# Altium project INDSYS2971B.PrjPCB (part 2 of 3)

## Sheet INDSYS2971B_BiasPower.SchDoc
size 431 x 279 mm; Date: Not shown in title block; ApprovedBy: Not shown in title block; CheckedBy: Not shown in title block; Author: Not shown in title block; CompanyName: Not shown in title block; DrawnBy: Battery test; Engineer: Not shown in title block; Organization: Not shown in title block; Address1: Not shown in title block; Address2: Not shown in title block; Address3: Not shown in title block; Address4: Not shown in title block; DocumentNumber: 10; Revision: Use project parameter SCH_Rev; SheetNumber: 10; SheetTotal: 11; PageSetup: Record=PageOptions¦CenterHorizontal=True¦CenterVertical=True¦PrintScale=1.00¦XCorrection=1.00¦YCorrection=1.00¦PrintKind=0¦BorderSize=5000000¦LeftOffset=0¦BottomOffset=0¦Orientation=2¦PaperLength=1000¦PaperWidth=1000¦Scale=100¦PaperSource=15¦PrintQuality=600¦MediaType=1¦DitherType=10¦PaperKind=Letter¦PrintScaleMode=1
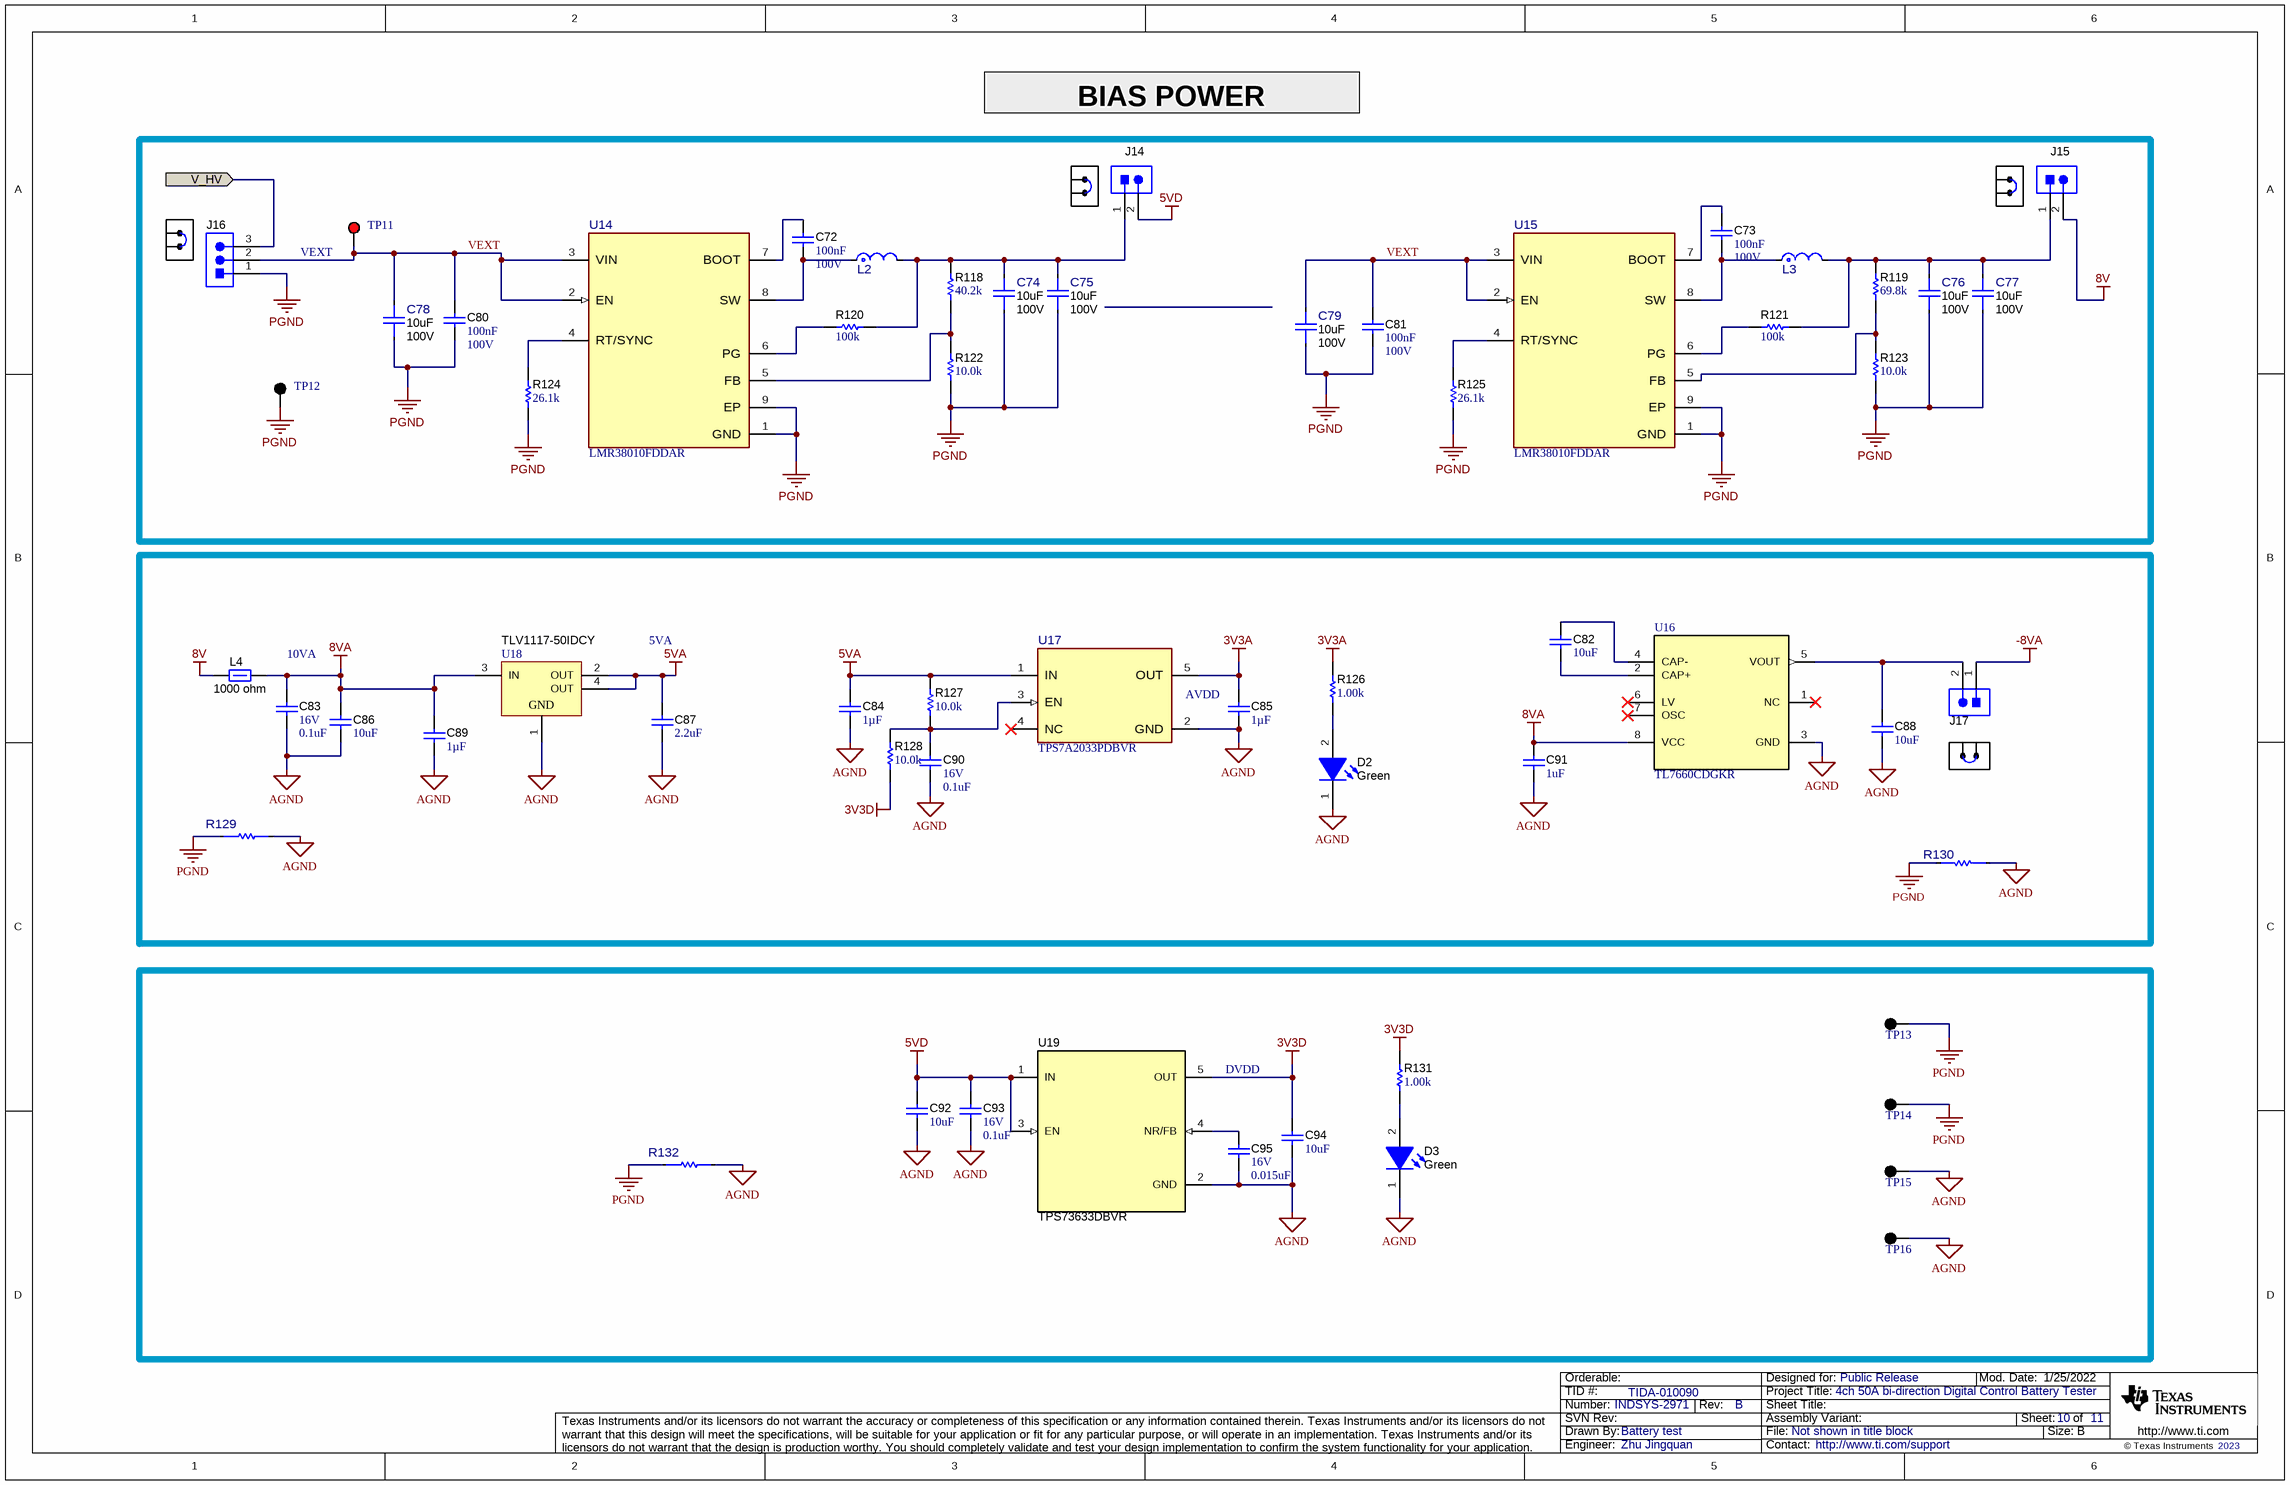
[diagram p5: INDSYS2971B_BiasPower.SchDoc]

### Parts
C72  Cap_F: 100nF  VDC_V: 100V  [0603]  (hidden comment: GRM188R72A104KA35D)
C73  Cap_F: 100nF  VDC_V: 100V  [0603]  (hidden comment: GRM188R72A104KA35D)
C74  ValueDisplayed: 10uF  VDC_V: 100V  [FP-GRM32EC72A106KE05L_1210-MFG]  (hidden comment: GRM32EC72A106KE05L)
C75  ValueDisplayed: 10uF  VDC_V: 100V  [FP-GRM32EC72A106KE05L_1210-MFG]  (hidden comment: GRM32EC72A106KE05L)
C76  ValueDisplayed: 10uF  VDC_V: 100V  [FP-GRM32EC72A106KE05L_1210-MFG]  (hidden comment: GRM32EC72A106KE05L)
C77  ValueDisplayed: 10uF  VDC_V: 100V  [FP-GRM32EC72A106KE05L_1210-MFG]  (hidden comment: GRM32EC72A106KE05L)
C78  ValueDisplayed: 10uF  VDC_V: 100V  [FP-GRM32EC72A106KE05L_1210-MFG]  (hidden comment: GRM32EC72A106KE05L)
C79  ValueDisplayed: 10uF  VDC_V: 100V  [FP-GRM32EC72A106KE05L_1210-MFG]  (hidden comment: GRM32EC72A106KE05L)
C80  Cap_F: 100nF  VDC_V: 100V  [0603]  (hidden comment: GRM188R72A104KA35D)
C81  Cap_F: 100nF  VDC_V: 100V  [0603]  (hidden comment: GRM188R72A104KA35D)
C82  ValueDisplayed: 10uF  [0603]  (hidden comment: GRM188R61E106MA73D)
C83  VDC_V: 16V  ValueDisplayed: 0.1uF  [0402]  (hidden comment: GRM155R61C104KA88D)
C84  ValueDisplayed: 1µF  [0603S]  (hidden comment: CGA3E1X7R1E105K080AC)
C85  ValueDisplayed: 1µF  [0603S]  (hidden comment: CGA3E1X7R1E105K080AC)
C86  ValueDisplayed: 10uF  [0603]  (hidden comment: GRM188R61E106MA73D)
C87  ValueDisplayed: 2.2uF  [0603S]  (hidden comment: F381A225MMA)
C88  ValueDisplayed: 10uF  [0603]  (hidden comment: GRM188R61E106MA73D)
C89  ValueDisplayed: 1µF  [0603S]  (hidden comment: CGA3E1X7R1E105K080AC)
C90  VDC_V: 16V  ValueDisplayed: 0.1uF  [0402]  (hidden comment: GRM155R61C104KA88D)
C91  ValueDisplayed: 1uF  [0805_HV]  (hidden comment: C2012X7S2A105K125AB)
C92  ValueDisplayed: 10uF  [0603]  (hidden comment: GRM188R61E106MA73D)
C93  VDC_V: 16V  ValueDisplayed: 0.1uF  [0402]  (hidden comment: GRM155R61C104KA88D)
C94  ValueDisplayed: 10uF  [0603]  (hidden comment: GRM188R61E106MA73D)
C95  VDC_V: 16V  ValueDisplayed: 0.015uF  [0402]  (hidden comment: GRM155R71C153KA01D)
D2  value Green  [WL-SMCW_GREEN]  (hidden comment: 150060VS75000)
D3  value Green  [WL-SMCW_GREEN]  (hidden comment: 150060VS75000)
J14  HTSW-102-07-G-S  [Samtec_HTSW-102-07-G-S]  (value not drawn)
J15  HTSW-102-07-G-S  [Samtec_HTSW-102-07-G-S]  (value not drawn)
J16  HTSW-103-07-G-S  [Samtec_HTSW-103-07-G-S]  (value not drawn)
J17  HTSW-102-07-G-S  [Samtec_HTSW-102-07-G-S]  (value not drawn)
L2  XGL6060-223MEC  [FP-XGL6060-223MEC_SMT2_6MM51_6MM71-MFG]  (value not drawn)
L3  XGL6060-223MEC  [FP-XGL6060-223MEC_SMT2_6MM51_6MM71-MFG]  (value not drawn)
L4  value 1000 ohm  [1806_HighSpeed]  (hidden comment: BLM41PG102SN1L)
R118  ValueDisplayed: 40.2k  [0402]  (hidden comment: CRCW040240K2FKED)
R119  ValueDisplayed: 69.8k  [0402]  (hidden comment: MCR01MZPF6982)
R120  ValueDisplayed: 100k  [0402]  (hidden comment: RC0402FR-07100KL)
R121  ValueDisplayed: 100k  [0402]  (hidden comment: RC0402FR-07100KL)
R122  ValueDisplayed: 10.0k  [0402]  (hidden comment: ERJPA2F1002X)
R123  ValueDisplayed: 10.0k  [0402]  (hidden comment: ERJPA2F1002X)
R124  ValueDisplayed: 26.1k  [0603]  (hidden comment: RC0603FR-0726K1L)
R125  ValueDisplayed: 26.1k  [0603]  (hidden comment: RC0603FR-0726K1L)
R126  ValueDisplayed: 1.00k  [0402]  (hidden comment: ERA-2AEB102X)
R127  ValueDisplayed: 10.0k  [0402]  (hidden comment: PCF0402-12-10K0BT1)
R128  ValueDisplayed: 10.0k  [0402]  (hidden comment: PCF0402-12-10K0BT1)
R129  CRCW12060000Z0EAC  [FP-CRCW12060000Z0EAC_1206-MFG]  (value not drawn)
R130  CRCW12060000Z0EAC  [FP-CRCW12060000Z0EAC_1206-MFG]  (value not drawn)
R131  ValueDisplayed: 1.00k  [0402]  (hidden comment: ERA-2AEB102X)
R132  CRCW12060000Z0EAC  [FP-CRCW12060000Z0EAC_1206-MFG]  (value not drawn)
SH-J2  60900213421  [Wurth_60900213421]  (value not drawn)
SH-J3  60900213421  [Wurth_60900213421]  (value not drawn)
SH-J4  60900213421  [Wurth_60900213421]  (value not drawn)
SH-J5  60900213421  [Wurth_60900213421]  (value not drawn)
TP11  5000  [Keystone5000]  (value not drawn)
TP12  5001  [Keystone5001]  (value not drawn)
TP13  5001  [Keystone5001]  (value not drawn)
TP14  5001  [Keystone5001]  (value not drawn)
TP15  5001  [Keystone5001]  (value not drawn)
TP16  5001  [Keystone5001]  (value not drawn)
U14  LMR38010FDDAR  [DDA0008E-MFG]
U15  LMR38010FDDAR  [DDA0008E-MFG]
U16  TL7660CDGKR  [DGK0008A_N]
U17  TPS7A2033PDBVR  [DBV0005A-MFG]
U18  PartNumber: TLV1117-50IDCY  [DCY0004A_N]  (hidden comment: TLV1117LV30DCYR)
U19  TPS73633DBVR  [DBV0005A_N]

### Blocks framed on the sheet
VEXT: C72-C81 J14-J16 L2 L3 R118-R125 SH-J2-SH-J4 TP11 TP12 U14 U15
DVDD: C92-C95 D3 R131 R132 TP13-TP16 U19

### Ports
V_HV (in)

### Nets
3V3A: C85.1 R126.2 U17.5(OUT)
3V3D: C94.1 R128.1 R131.2 U19.5(OUT)
5VA: C84.1 C87.1 R127.2 U17.1(IN) U18.2(OUT) U18.4(OUT)
5VD: C92.1 C93.2 J14.2 U19.1(IN) U19.3(EN)
8V: J15.2 L4.1
8VA: C83.2 C86.1 C89.1 C91.1 L4.2 U16.8(VCC) U18.3(IN)
-8VA: J17.1
AGND: C83.1 C84.2 C85.2 C86.2 C87.2 C88.2 C89.2 C90.1 C91.2 C92.2 C93.1 C94.2 C95.2 D2.1(K) D3.1(K) R129.2 R130.1 R132.2 TP15.1 TP16.1 U16.3(GND) U17.2(GND) U18.1(GND) U19.2(GND)
PGND: C74.1 C75.1 C76.1 C77.1 C78.1 C79.1 C80.2 C81.2 J16.1 R122.1 R123.1 R124.1 R125.1 R129.1 R130.2 R132.1 TP12.1 TP13.1 TP14.1 U14.1(GND) U14.9(EP) U15.1(GND) U15.9(EP)
V_HV: J16.3 ; port V_HV
VEXT: C78.2 C79.2 C80.1 C81.1 J16.2 TP11.1 U14.2(EN) U14.3(VIN) U15.2(EN) U15.3(VIN)
NetC72_1: C72.1 U14.7(BOOT)
NetC72_2: C72.2 L2.1 U14.8(SW)
NetC73_1: C73.1 U15.7(BOOT)
NetC73_2: C73.2 L3.1 U15.8(SW)
NetC74_2: C74.2 C75.2 J14.1 L2.2 R118.2 R120.2
NetC76_2: C76.2 C77.2 J15.1 L3.2 R119.2 R121.2
NetC82_1: C82.1 U16.4(CAP-)
NetC82_2: C82.2 U16.2(CAP+)
NetC88_1: C88.1 J17.2 U16.5(VOUT)
NetC90_2: C90.2 R127.1 R128.2 U17.3(EN)
NetC95_1: C95.1 U19.4(NR/FB)
NetD2_2: D2.2(A) R126.1
NetD3_2: D3.2(A) R131.1
NetR118_1: R118.1 R122.2 U14.5(FB)
NetR119_1: R119.1 R123.2 U15.5(FB)
NetR120_1: R120.1 U14.6(PG)
NetR121_1: R121.1 U15.6(PG)
NetR124_2: R124.2 U14.4(RT/SYNC)
NetR125_2: R125.2 U15.4(RT/SYNC)

Not connected (* = marked no-connect by the designer): U16 1(NC)* 6(LV)* 7(OSC)*; U17 4(NC)*

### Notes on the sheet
- BIAS POWER
- 10VA
- 5VA
- (near U17) AVDD

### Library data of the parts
C72 C73 C80 C81 = CMP-0007469-4: CAP, CERM, 0.1 uF, 100 V, +/- 10%, X7R, 0603; Manufacturer: MuRata; TaMin_C: -55°C; Polarized: N; SizeAreaWB_mm2: 4.68; Value1: Unknown; U/M: EA; Value: 0.1uF; TaMax_C: 125°C; SizeZ_mm: 1; SizeX_mm: 1.6; SizeY_mm: 0.8; SizeArea_mm2: 1.28; AEC Category: Q200
C74-C79 = CMP-0087970-1: 10µF ±10% 100V Ceramic Capacitor X7S 1210 (3225 Metric); Manufacturer: Murata; Symbol Name: SYM-GRM32EC72A106KE05L; AEC Qualified: No; TempCo: 22%; SizeZ_mm: 2.7mm
C82 C86 C88 C92 C94 = CMP-0007344-5: CAP, CERM, 10 uF, 25 V, +/- 20%, X5R, 0603; Manufacturer: MuRata; Polarized: N; Value: 10uF; U/M: EA; Cap_F: 10µF; Value1: Unknown; VDC_V: 25V; TaMin_C: -55°C; TaMax_C: 85°C; SizeArea_mm2: 1.28; SizeAreaWB_mm2: 4.68; SizeX_mm: 1.6; SizeY_mm: 0.8; SizeZ_mm: 1; AEC Category: Q200
C83 C90 C93 = CMP-0006591-2: CAP, CERM, 0.1 uF, 16 V, +/- 10%, X5R, 0402; Manufacturer: MuRata; TaMin_C: -55°C; Polarized: N; SizeAreaWB_mm2: 3; Value1: Unknown; U/M: EA; Value: 0.1uF; TaMax_C: 85°C; SizeZ_mm: 0.6; SizeX_mm: 1; SizeY_mm: 0.5; Cap_F: 100nF; AEC Category: Q200
C84 C85 C89 = CMP-0076705-3: CAP, CERM, 1 µF, 25 V,+/- 10%, X7R, AEC-Q200 Grade 1, 0603; Manufacturer: TDK; Polarized: N; Value: 1uF; U/M: EA; VDC_V: 25V; TaMin_C: -55°C; TaMax_C: 125°C; Cap_Case: 1.6x0.8x0.8mm; SizeAreaWB_mm2: 4.68; SizeArea_mm2: 1.28; AEC Qualified: Y; AEC Category: Q200; SizeZ_mm: 1.0; AEC Grade: 1; SizeY_mm: 0.8; SizeX_mm: 1.6
C87 = CMP-0076705-3: CAP TANT POLY 2.2UF 10V 0603; Manufacturer: KYOCERA AVX; Polarized: N; U/M: EA; Tolerance_%: 20%; ESR_ohm: 0.2; TempCo: X7R; TaMin_C: -55°C; TaMax_C: 125°C; Cap_Case: 1.6x0.8x0.8mm; SizeAreaWB_mm2: 4.68; SizeArea_mm2: 1.28; AEC Qualified: Y; AEC Category: Q200; SizeZ_mm: 1.0; AEC Grade: 1; SizeY_mm: 0.8; SizeX_mm: 1.6
C91 = CMP-0007891-2: CAP, CERM, 1 uF, 100 V, +/- 10%, X7S, 0805; Manufacturer: TDK; Polarized: N; Value: 1uF; U/M: EA; Cap_F: 1µF; ESR_ohm: 8.255m; Value1: 0.008255 ohm; VDC_V: 100V; IRMS_A: 2.2744A; TaMin_C: -55°C; TaMax_C: 125°C; Cap_Case: 0805; AEC Category: Q200; SizeArea_mm2: 2.5; SizeAreaWB_mm2: 6.75; SizeX_mm: 2; SizeY_mm: 1.25; SizeZ_mm: 1.45
C95 = CMP-0006644-2: CAP, CERM, 0.015 uF, 16 V, +/- 10%, X7R, 0402; Manufacturer: MuRata; TaMin_C: -55°C; Polarized: N; SizeAreaWB_mm2: 3; Value1: Unknown; U/M: EA; TaMax_C: 125°C; SizeZ_mm: 0.6; SizeX_mm: 1; SizeY_mm: 0.5; Cap_F: 15nF; AEC Category: Q200
D2 D3 = CMP-0002894-2: LED, Green, SMD; Manufacturer: Wurth Elektronik; Type: AlInGaP; Vf_V: 2V; Io_A: 20mA; Value1: W
J14 J15 J17 = CMP-0075483-1: Header, 100mil, 2x1, Gold, TH; Manufacturer: Samtec; Green_REACh: Passed; CT: False; Green_Lifecycle: Active; CNHeader: True
J16 = CMP-0075484-1: Header, 100mil, 3x1, Gold, TH; Manufacturer: Samtec; Green_REACh: Passed; CT: False; Green_Lifecycle: Active; CNHeader: True
L2 L3 = CMP-0095453-1: 22 µH Shielded Inductor 5.8 A 46.9mOhm Max Nonstandard; Manufacturer: Coilcraft; Isat: 2.5A; Test Frequency: 1MHz; SizeZ_mm: 6.1mm; Self Resonant Frequency: 9MHz; Value: 22uH; Irms: 5.8A; DCR_ohm: 46.9m; Ind_H: 22µH; Material: Composite; AEC Qualified: Yes; AEC Grade: Grade 1; TaMax_C: +125°C; Tolerance_%: 20%; Shrouded: true; TaMin_C: -40°C
L4 = CMP-0003369-1: Ferrite Bead, 1000 ohm @ 100 MHz, 1.5 A, 1806; Manufacturer: MuRata; ZTyp@100MHz_Ohm: 1k; SizeAreaWB_mm2: 14.3; DCR_ohm: 0.09; Value1: 0.09 ohm; Imax_A: 1.5A; SizeZ_mm: 1.85; SizeX_mm: 4.5; SizeY_mm: 1.6; SizeArea_mm2: 7.2
R118 = CMP-0026367-2: RES, 40.2 k, 1%, 0.063 W, AEC-Q200 Grade 0, 0402; Manufacturer: Vishay-Dale; Power_W: 63mW; TempCo: 100 ppm/C; Value_Code: 40k2; Value: 40.2k; EIA_Code: E96; SizeX_mm: 1; SizeY_mm: 0.5; SizeZ_mm: 0.6; Value2: 0.063W; AEC Qualified: Y; VDC_V: 50V; AEC Category: Q200; AEC Grade: 0
R119 = CMP-0026720-1: RES, 69.8 k, 1%, 0.063 W, 0402; Manufacturer: Rohm; Power_W: 63mW; TempCo: 100 ppm/C; Value_Code: 69k8; U/M: EA; Value: 69.8k; EIA_Code: E96; SizeX_mm: 1; SizeY_mm: 0.5; SizeZ_mm: 0.6; Value2: 0.063W; AEC Qualified: N; VDC_V: 50V; AEC Category: Q200
R120 R121 = CMP-0026721-1: RES, 100 k, 1%, 0.0625 W, 0402; Manufacturer: Yageo America; Power_W: 62.5mW; TempCo: 100 ppm/C; U/M: EA; Value: 100k; EIA_Code: E96; SizeX_mm: 1; SizeY_mm: 0.5; SizeZ_mm: 0.6; AEC Qualified: N; VDC_V: 50V; AEC Category: Q200
R122 R123 = CMP-0078779-1: RES, 10.0 k, 1%, 0.2 W, AEC-Q200 Grade 0, 0402; Manufacturer: Panasonic; Value_Code: 10k0; SizeArea_mm2: 0.5; AEC Qualified: Y; AEC Category: Q200; Res_ohm: 10k; Value: 10.0k; SizeZ_mm: 0.6; EIA_Code: E96; TempCo: 100 ppm/C; AEC Grade: 0; Power_W: 200mW; VDC_V: 50V; Value2: 0.2W; SizeX_mm: 1
R124 R125 = CMP-0022957-5: RES, 26.1 k, 1%, 0.1 W, 0603; Manufacturer: Yageo; Power_W: 100mW; TempCo: 100 ppm/C; Value_Code: 26k1; Value: 26.1k; EIA_Code: E96; SizeX_mm: 1.6; SizeY_mm: 0.8; SizeZ_mm: 1; Value2: 0.1W; SizeArea_mm2: 1.28; AEC Qualified: N; VDC_V: 75V; AEC Category: Q200; SizeAreaWB_mm2: 4.68
R126 R131 = CMP-0026770-1: RES, 1.00 k, 0.1%, 0.063 W, 0402; Manufacturer: Panasonic; Power_W: 63mW; TempCo: 25 ppm/C; Value_Code: 1k00; U/M: EA; Value: 1.00k; EIA_Code: E192; Res_ohm: 1k; SizeX_mm: 1; SizeY_mm: 0.5; SizeZ_mm: 0.6; Value2: 0.063W; VDC_V: 50V; AEC Category: Q200
R127 = CMP-0026796-1: RES, 10.0 k, 0.1%, 0.063 W, 0402; Manufacturer: TT Electronics/IRC; Power_W: 63mW; TempCo: 10 ppm/C; Value_Code: 10k0; Value: 10.0k; Res_ohm: 10k; SizeX_mm: 1; SizeY_mm: 0.5; SizeZ_mm: 0.6; Value2: 0.063W; AEC Qualified: N; VDC_V: 25V; AEC Category: Q200; EIA_Code: E192; U/M: EA
R128 = CMP-0026796-1: RES, 10.0 k, 0.1%, 0.063 W, 0402; Manufacturer: TT Electronics/IRC; Power_W: 63mW; TempCo: 10 ppm/C; Value_Code: 10k0; Value: 10.0k; EIA_Code: E192; Res_ohm: 10k; SizeX_mm: 1; SizeY_mm: 0.5; SizeZ_mm: 0.6; Value2: 0.063W; AEC Qualified: N; VDC_V: 25V; AEC Category: Q200; U/M: EA
R129 R130 R132 = CMP-0094724-1: Jumper 0.25W, 1/4W Chip Resistor 1206 (3216 Metric) - Thick Film; Manufacturer: Vishay; Value: 0; Power_W: 250mW; VDC_V: 200V; SizeZ_mm: 0.65mm; AEC Qualified: No
SH-J2-SH-J5 = CMP-0003761-2: Shunt, 2.54mm, Gold, Black; Manufacturer: Wurth Elektronik
TP11 = CMP-0055137-2: Test Point, Miniature, Red, TH; Manufacturer: Keystone Electronics; Green_REACh: Passed; Green_Lifecycle: Active; ContactFinish: Silver; CNHeader: FALSE; CT: TRUE
TP12-TP16 = CMP-0055138-2: Test Point, Miniature, Black, TH; Manufacturer: Keystone Electronics; ContactFinish: Silver; Green_Lifecycle: Active; Green_REACh: Passed; CNHeader: FALSE; CT: TRUE
U14 U15 = CMP-0096892-1: 4.2-V to 80-V, 1-A Synchronous Buck Converter with 40-µA IQ; Manufacturer: Texas Instruments; Output Type: AdjustableProgrammable; AEC Qualified: No; Output Voltage: 1-75V; Standoff Height: 0mm; Nominal Supply Current: 40uA; Number Of Outputs: 1; TJmax_C: +150°C; Switching Frequency: 200-2200kHz; Min Supply Voltage: 4.2V; Max Duty Cycle: 97%; Max Supply Voltage: 80V; SizeZ_mm: 1.7mm
U16 = CMP-0041281-2: CMOS Voltage Converter, DGK0008A (VSSOP-8); Manufacturer: Texas Instruments; Total Supply Voltage(Min)(+5V is 5, +/-5V is 10): 1.5; Sub Family: Low Power Amp (<=500uA), Low Supply Voltage Amplifier (<=2.7V), Precision Amplifier; Total Supply Voltage(Max)(+5V is 5, +/-5V is 10): 10; Iq per channel(Max)(mA): 0.11; Number of Channels: 1; AEC Category: Q200; AEC Qualified: N; CompType: IC; SizeAreaWB_mm2: 23.6; SizeArea_mm2: 14.7; SizeX_mm: 4.9; SizeY_mm: 3; SizeZ_mm: 1.1
U17 = CMP-0092532-1: 300-mA, Ultra-Low-Noise, Low-IQ, High PSRR LDO; Manufacturer: Texas Instruments; TJmax_C: +125°C; Min Supply Voltage: 1.6V; SizeZ_mm: 1.45mm; Output Voltage: 3.3V; Number Of Outputs: 1; Nominal Supply Current: 6.5uA; AEC Qualified: No; Accuracy Percentage: 1.5%; Max Supply Voltage: 6V; Dropout Voltage: 145mV; Standoff Height: 0mm; Output Type: Fixed
U18 = CMP-0036758-1: Single Output LDO, 1 A, Fixed 5 V Output, 2 to 5.5 V Input, 4-pin SOT-223 (DCY), -40 to 125 degC, Green (RoHS & no Sb/Br); Manufacturer: Texas Instruments; Vout Adj(Max)(V): 3; Iq(Typ)(mA): 0.05; Vin(Max)(V): 5.5; Accuracy(%): 2; SubFamily: Single Channel LDO; Vdo(Typ)(mV): 1200; Iout(Max)(A): 1
U19 = CMP-0036866-2: Single Output Low Noise LDO, 400 mA, Fixed 3.3 V Output, 1.7 to 5.5 V Input, with Reverse Current Protection, 5-pin SOT-23 (DBV), -40 to 85 degC, Green (RoHS & no Sb/Br); Manufacturer: Texas Instruments; Alternate PartNumber: TPS73633DBVT; Vout Adj(Min)(V): 3.3; Rating: Catalog; Accuracy(%): 1; Iq(Typ)(mA): 0.3; Vin(Max)(V): 5.5; SubFamily: Single Channel LDO; Vdo(Typ)(mV): 75; Vin(Min)(V): 1.7; Iout(Max)(A): 0.4; AEC Category: Q200; AEC Qualified: N; CompType: IC; Green_Lifecycle: Active; Green_REACh: Passed; SizeAreaWB_mm2: 14.82; SizeArea_mm2: 8.12; SizeX_mm: 2.8; SizeY_mm: 2.9; SizeZ_mm: 1.45

## Sheet INDSYS2971B_ControlCard.SchDoc
size 431 x 279 mm; Date: Not shown in title block; ApprovedBy: Not shown in title block; CheckedBy: Not shown in title block; Author: Not shown in title block; CompanyName: Not shown in title block; DrawnBy: Battery test; Engineer: Not shown in title block; Organization: Not shown in title block; Address1: Not shown in title block; Address2: Not shown in title block; Address3: Not shown in title block; Address4: Not shown in title block; DocumentNumber: 9; Revision: Use project parameter SCH_Rev; SheetNumber: 9; SheetTotal: 11; PageSetup: Record=PageOptions¦CenterHorizontal=True¦CenterVertical=True¦PrintScale=1.00¦XCorrection=1.00¦YCorrection=1.00¦PrintKind=0¦BorderSize=5000000¦LeftOffset=0¦BottomOffset=0¦Orientation=2¦PaperLength=1000¦PaperWidth=1000¦Scale=100¦PaperSource=15¦PrintQuality=600¦MediaType=1¦DitherType=10¦PaperKind=Letter¦PrintScaleMode=1
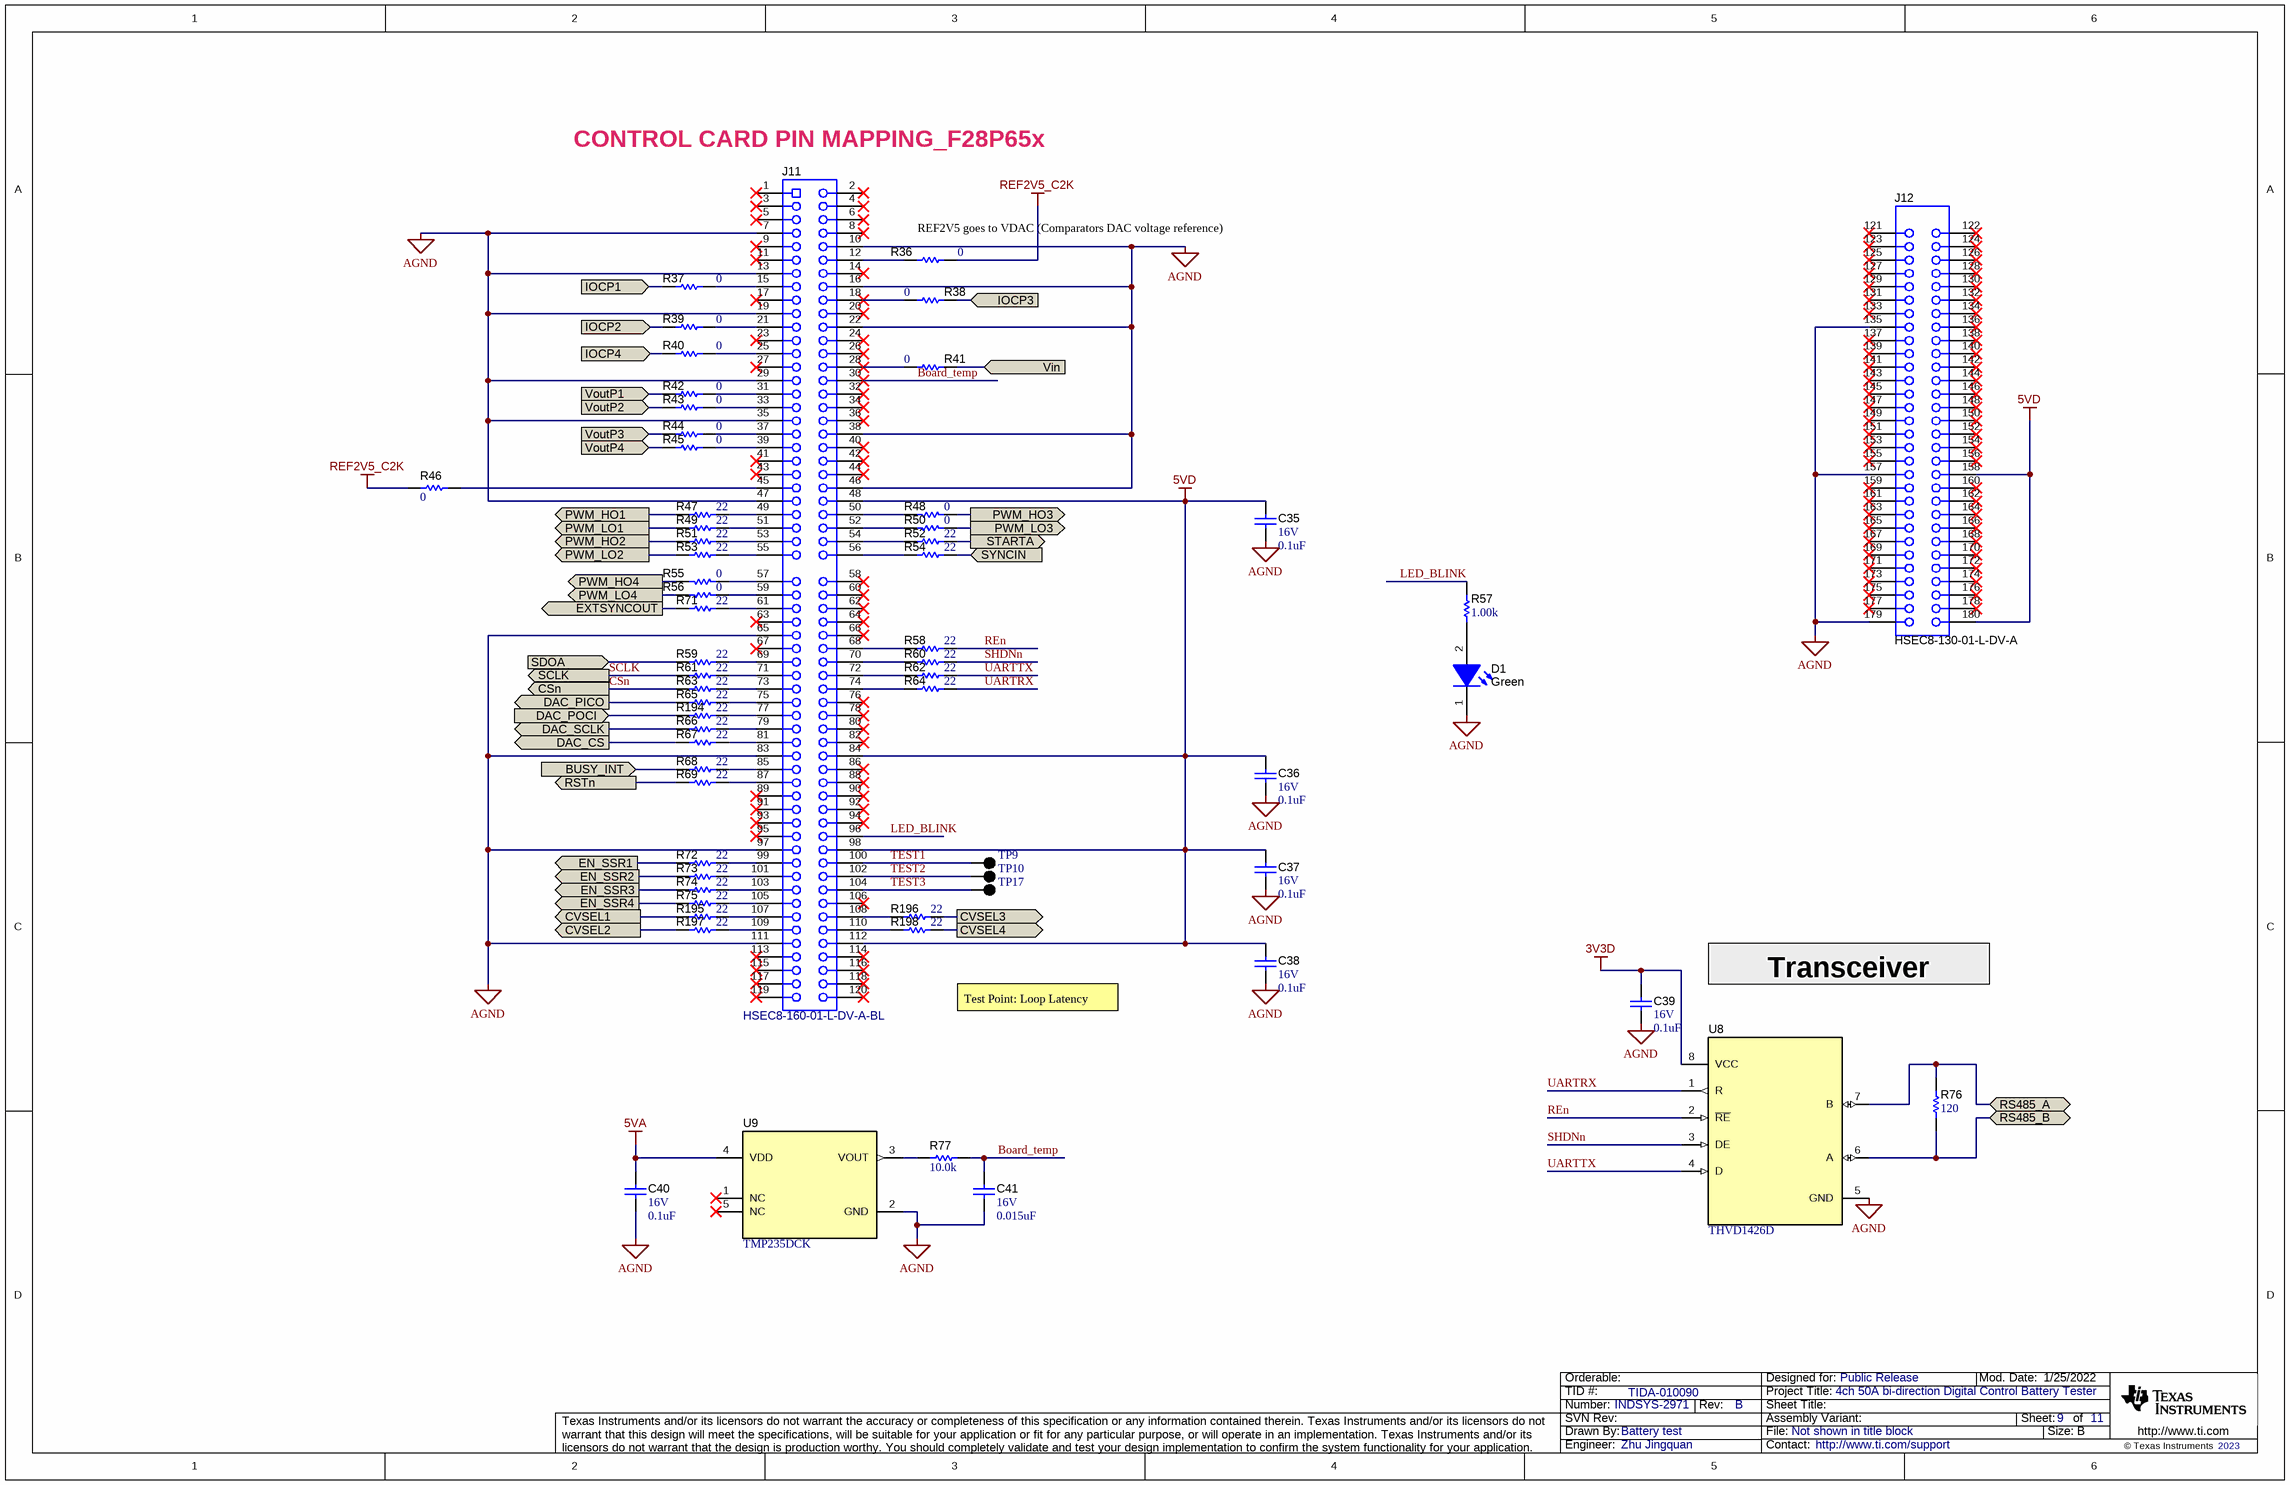
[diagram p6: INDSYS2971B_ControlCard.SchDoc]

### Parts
C35  VDC_V: 16V  ValueDisplayed: 0.1uF  [0402]  (hidden comment: GRM155R61C104KA88D)
C36  VDC_V: 16V  ValueDisplayed: 0.1uF  [0402]  (hidden comment: GRM155R61C104KA88D)
C37  VDC_V: 16V  ValueDisplayed: 0.1uF  [0402]  (hidden comment: GRM155R61C104KA88D)
C38  VDC_V: 16V  ValueDisplayed: 0.1uF  [0402]  (hidden comment: GRM155R61C104KA88D)
C39  VDC_V: 16V  ValueDisplayed: 0.1uF  [0402]  (hidden comment: GRM155R61C104KA88D)
C40  VDC_V: 16V  ValueDisplayed: 0.1uF  [0402]  (hidden comment: GRM155R61C104KA88D)
C41  VDC_V: 16V  ValueDisplayed: 0.015uF  [0402]  (hidden comment: GRM155R71C153KA01D)
D1  value Green  [WL-SMCW_GREEN]  (hidden comment: 150060VS75000)
J11  HSEC8-160-01-L-DV-A-BL  [controlCARD-120HSEC]
J12  HSEC8-130-01-L-DV-A  [controlCARD-180HSEC-60pinAddon]
R36  ValueDisplayed: 0  [0402]  (hidden comment: CRCW04020000Z0ED)
R37  ValueDisplayed: 0  [0402]  (hidden comment: CRCW04020000Z0ED)
R38  ValueDisplayed: 0  [0402]  (hidden comment: CRCW04020000Z0ED)
R39  ValueDisplayed: 0  [0402]  (hidden comment: CRCW04020000Z0ED)
R40  ValueDisplayed: 0  [0402]  (hidden comment: CRCW04020000Z0ED)
R41  ValueDisplayed: 0  [0402]  (hidden comment: CRCW04020000Z0ED)
R42  ValueDisplayed: 0  [0402]  (hidden comment: CRCW04020000Z0ED)
R43  ValueDisplayed: 0  [0402]  (hidden comment: CRCW04020000Z0ED)
R44  ValueDisplayed: 0  [0402]  (hidden comment: CRCW04020000Z0ED)
R45  ValueDisplayed: 0  [0402]  (hidden comment: CRCW04020000Z0ED)
R46  ValueDisplayed: 0  [0402]  (hidden comment: CRCW04020000Z0ED)
R47  ValueDisplayed: 22  [0402]  (hidden comment: CRCW040222R0JNED)
R48  ValueDisplayed: 0  [0402]  (hidden comment: CRCW04020000Z0ED)
R49  ValueDisplayed: 22  [0402]  (hidden comment: CRCW040222R0JNED)
R50  ValueDisplayed: 0  [0402]  (hidden comment: CRCW04020000Z0ED)
R51  ValueDisplayed: 22  [0402]  (hidden comment: CRCW040222R0JNED)
R52  ValueDisplayed: 22  [0402]  (hidden comment: CRCW040222R0JNED)
R53  ValueDisplayed: 22  [0402]  (hidden comment: CRCW040222R0JNED)
R54  ValueDisplayed: 22  [0402]  (hidden comment: CRCW040222R0JNED)
R55  ValueDisplayed: 0  [0402]  (hidden comment: CRCW04020000Z0ED)
R56  ValueDisplayed: 0  [0402]  (hidden comment: CRCW04020000Z0ED)
R57  ValueDisplayed: 1.00k  [0402]  (hidden comment: ERA-2AEB102X)
R58  ValueDisplayed: 22  [0402]  (hidden comment: CRCW040222R0JNED)
R59  ValueDisplayed: 22  [0402]  (hidden comment: CRCW040222R0JNED)
R60  ValueDisplayed: 22  [0402]  (hidden comment: CRCW040222R0JNED)
R61  ValueDisplayed: 22  [0402]  (hidden comment: CRCW040222R0JNED)
R62  ValueDisplayed: 22  [0402]  (hidden comment: CRCW040222R0JNED)
R63  ValueDisplayed: 22  [0402]  (hidden comment: CRCW040222R0JNED)
R64  ValueDisplayed: 22  [0402]  (hidden comment: CRCW040222R0JNED)
R65  ValueDisplayed: 22  [0402]  (hidden comment: CRCW040222R0JNED)
R66  ValueDisplayed: 22  [0402]  (hidden comment: CRCW040222R0JNED)
R67  ValueDisplayed: 22  [0402]  (hidden comment: CRCW040222R0JNED)
R68  ValueDisplayed: 22  [0402]  (hidden comment: CRCW040222R0JNED)
R69  ValueDisplayed: 22  [0402]  (hidden comment: CRCW040222R0JNED)
R71  ValueDisplayed: 22  [0402]  (hidden comment: CRCW040222R0JNED)
R72  ValueDisplayed: 22  [0402]  (hidden comment: CRCW040222R0JNED)
R73  ValueDisplayed: 22  [0402]  (hidden comment: CRCW040222R0JNED)
R74  ValueDisplayed: 22  [0402]  (hidden comment: CRCW040222R0JNED)
R75  ValueDisplayed: 22  [0402]  (hidden comment: CRCW040222R0JNED)
R76  ValueDisplayed: 120  [0402]  (hidden comment: CRCW0402120RJNED)
R77  ValueDisplayed: 10.0k  [0402]  (hidden comment: PCF0402-12-10K0BT1)
R194  ValueDisplayed: 22  [0402]  (hidden comment: CRCW040222R0JNED)
R195  ValueDisplayed: 22  [0402]  (hidden comment: CRCW040222R0JNED)
R196  ValueDisplayed: 22  [0402]  (hidden comment: CRCW040222R0JNED)
R197  ValueDisplayed: 22  [0402]  (hidden comment: CRCW040222R0JNED)
R198  ValueDisplayed: 22  [0402]  (hidden comment: CRCW040222R0JNED)
TP9  5001  [Keystone5001]  (value not drawn)
TP10  5001  [Keystone5001]  (value not drawn)
TP17  5001  [Keystone5001]  (value not drawn)
U8  THVD1426D  [D0008A_N]
U9  TMP235DCK  [DCK0005A_N]

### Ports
BUSY_INT (in), CSn (out), CVSEL1 (out), CVSEL2 (out), CVSEL3 (out), CVSEL4 (out), DAC_CS (out), DAC_PICO (out), DAC_POCI (in), DAC_SCLK (out), EN_SSR1 (out), EN_SSR2 (out), EN_SSR3 (out), EN_SSR4 (out), EXTSYNCOUT (out), IOCP1 (in), IOCP2 (in), IOCP3 (in), IOCP4 (in), PWM_HO1 (out), PWM_HO2 (out), PWM_HO3 (out), PWM_HO4 (out), PWM_LO1 (out), PWM_LO2 (out), PWM_LO3 (out), PWM_LO4 (out), RS485_A (bidir), RS485_B (bidir), RSTn (out), SCLK (out), SDOA (in), STARTA (out), SYNCIN (in), Vin (in), VoutP1 (in), VoutP2 (in), VoutP3 (in), VoutP4 (in)

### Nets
3V3D: C39.2 U8.8(VCC)
5VA: C40.2 U9.4(VDD)
5VD: C35.2 C36.2 C37.2 C38.2 J11.48 J11.84 J11.98 J11.112 J12.158 J12.180
AGND: C35.1 C36.1 C37.1 C38.1 C39.1 C40.1 C41.2 D1.1(K) J11.7 J11.10 J11.13 J11.16 J11.19 J11.22 J11.29 J11.35 J11.38 J11.46 J11.47 J11.65 J11.83 J11.97 J11.111 J12.135 J12.157 J12.179 U8.5(GND) U9.2(GND)
REF2V5_C2K: R36.1 R46.2
Board_temp: C41.1 J11.30 R77.1
BUSY_INT: R68.1 ; port BUSY_INT
CSn: R63.1 ; port CSn
CVSEL1: R195.1 ; port CVSEL1
CVSEL2: R197.1 ; port CVSEL2
CVSEL3: R196.2 ; port CVSEL3
CVSEL4: R198.2 ; port CVSEL4
DAC_CS: R67.1 ; port DAC_CS
DAC_PICO: R65.1 ; port DAC_PICO
DAC_POCI: R194.1 ; port DAC_POCI
DAC_SCLK: R66.1 ; port DAC_SCLK
EN_SSR1: R72.1 ; port EN_SSR1
EN_SSR2: R73.1 ; port EN_SSR2
EN_SSR3: R74.1 ; port EN_SSR3
EN_SSR4: R75.1 ; port EN_SSR4
IOCP1: R37.2 ; port IOCP1
IOCP2: R39.2 ; port IOCP2
IOCP3: R38.2 ; port IOCP3
IOCP4: R40.2 ; port IOCP4
LED_BLINK: J11.96 R57.2
PWM_HO1: R47.1 ; port PWM_HO1
PWM_HO2: R51.1 ; port PWM_HO2
PWM_HO3: R48.2 ; port PWM_HO3
PWM_HO4: R55.2 ; port PWM_HO4
PWM_LO1: R49.1 ; port PWM_LO1
PWM_LO2: R53.1 ; port PWM_LO2
PWM_LO3: R50.2 ; port PWM_LO3
PWM_LO4: R56.2 ; port PWM_LO4
REn: R58.2 U8.2(~{RE})
RSTn: R69.1 ; port RSTn
SCLK: R61.1 ; port SCLK
SDOA: R59.1 ; port SDOA
SHDNn: R60.2 U8.3(DE)
STARTA: R52.2 ; port STARTA
TEST1: J11.100 TP9.1
TEST2: J11.102 TP10.1
TEST3: J11.104 TP17.1
UARTRX: R64.2 U8.1(R)
UARTTX: R62.2 U8.4(D)
Vin: R41.2 ; port Vin
VoutP1: R42.2 ; port VoutP1
VoutP2: R43.2 ; port VoutP2
VoutP3: R44.2 ; port VoutP3
VoutP4: R45.2 ; port VoutP4
NetD1_2: D1.2(A) R57.1
NetJ3_1: R76.2 U8.7(B) ; port RS485_A
NetJ3_2: R76.1 U8.6(A) ; port RS485_B
NetJ11_12: J11.12 R36.2
NetJ11_15: J11.15 R37.1
NetJ11_18: J11.18 R38.1
NetJ11_21: J11.21 R39.1
NetJ11_25: J11.25 R40.1
NetJ11_28: J11.28 R41.1
NetJ11_31: J11.31 R42.1
NetJ11_33: J11.33 R43.1
NetJ11_37: J11.37 R44.1
NetJ11_39: J11.39 R45.1
NetJ11_45: J11.45 R46.1
NetJ11_49: J11.49 R47.2
NetJ11_50: J11.50 R48.1
NetJ11_51: J11.51 R49.2
NetJ11_52: J11.52 R50.1
NetJ11_53: J11.53 R51.2
NetJ11_54: J11.54 R52.1
NetJ11_55: J11.55 R53.2
NetJ11_56: J11.56 R54.1
NetJ11_57: J11.57 R55.1
NetJ11_59: J11.59 R56.1
NetJ11_61: J11.61 R71.1
NetJ11_68: J11.68 R58.1
NetJ11_69: J11.69 R59.2
NetJ11_70: J11.70 R60.1
NetJ11_71: J11.71 R61.2
NetJ11_72: J11.72 R62.1
NetJ11_73: J11.73 R63.2
NetJ11_74: J11.74 R64.1
NetJ11_75: J11.75 R65.2
NetJ11_77: J11.77 R194.2
NetJ11_79: J11.79 R66.2
NetJ11_81: J11.81 R67.2
NetJ11_85: J11.85 R68.2
NetJ11_87: J11.87 R69.2
NetJ11_99: J11.99 R72.2
NetJ11_101: J11.101 R73.2
NetJ11_103: J11.103 R74.2
NetJ11_105: J11.105 R75.2
NetJ11_107: J11.107 R195.2
NetJ11_108: J11.108 R196.1
NetJ11_109: J11.109 R197.2
NetJ11_110: J11.110 R198.1
NetR54_2: R54.2 ; port SYNCIN
NetR71_2: R71.2 ; port EXTSYNCOUT
NetR77_2: R77.2 U9.3(VOUT)

Not connected (* = marked no-connect by the designer): J11 1* 2* 3* 4* 5* 6* 8* 9* 11* 14* 17* 20* 23* 24* 26* 27* 32* 34* 36* 40* 41* 42* 43* 44* 58* 60* 62* 63* 64* 66* 67* 76* 78* 80* 82* 86* 88* 89* 90* 91* 92* 93* 94* 95* 106* 113* 114* 115* 116* 117* 118* 119* 120*; J12 121* 122* 123* 124* 125* 126* 127* 128* 129* 130* 131* 132* 133* 134* 136* 137* 138* 139* 140* 141* 142* 143* 144* 145* 146* 147* 148* 149* 150* 151* 152* 153* 154* 155* 156* 159* 160* 161* 162* 163* 164* 165* 166* 167* 168* 169* 170* 171* 172* 173* 174* 175* 176* 177* 178*; U9 1(NC)* 5(NC)*

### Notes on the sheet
- (near J11) CONTROL CARD PIN MAPPING_F28P65x
- (near R36) REF2V5 goes to VDAC (Comparators DAC voltage reference)
- Test Point: Loop Latency
- Transceiver

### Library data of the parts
C35-C40 = CMP-0006591-2: as C83 on sheet INDSYS2971B_BiasPower
C41 = CMP-0006644-2: as C95 on sheet INDSYS2971B_BiasPower
D1 = CMP-0002894-2: as D2 on sheet INDSYS2971B_BiasPower
J11 = CMP-0003814-2: C2000 controlCARD-120HSEC connector, SMT; Manufacturer: Samtec; Note: The pin numbering does not match Samtec datasheet
J12 = CMP-0003859-2: C2000 controlCARD-180HSEC (60-pin addon) connector, SMT; Manufacturer: Samtec; Note: The pin numbering does not match Samtec datasheet
R36-R46 R48 R50 R55 R56 = CMP-0026822-3: RES, 0, 5%, 0.063 W, AEC-Q200 Grade 0, 0402; Manufacturer: Vishay-Dale; Value: 0; Value_Code: 0000; Power_W: 63mW; Value2: 0.063W; VDC_V: 50V; TempCo: 200 ppm/C; SizeArea_mm2: 0.5; SizeX_mm: 1; SizeZ_mm: 0.6; EIA_Code: E24; AEC Category: Q200; AEC Qualified: Y
R47 R49 R51-R54 R58-R69 R71-R75 R194-R198 = CMP-0026880-3: RES, 22, 5%, 0.063 W, AEC-Q200 Grade 0, 0402; Manufacturer: Vishay-Dale; Power_W: 63mW; TempCo: 200 ppm/C; Value_Code: 22R0; Value: 22; EIA_Code: E24; SizeX_mm: 1; SizeY_mm: 0.5; SizeZ_mm: 0.6; Value2: 0.063W; AEC Qualified: Y; VDC_V: 50V; AEC Category: Q200; AEC Grade: 0
R57 = CMP-0026770-1: as R126 on sheet INDSYS2971B_BiasPower
R76 = CMP-0026833-3: RES, 120, 5%, 0.063 W, AEC-Q200 Grade 0, 0402; Manufacturer: Vishay-Dale; Power_W: 63mW; TempCo: 200 ppm/C; Value_Code: 120R; Value: 120; EIA_Code: E24; SizeX_mm: 1; SizeY_mm: 0.5; SizeZ_mm: 0.6; Value2: 0.063W; AEC Qualified: Y; VDC_V: 50V; AEC Category: Q200; AEC Grade: 0
R77 = CMP-0026796-1: RES, 10.0 k, 0.1%, 0.063 W, 0402; Manufacturer: TT Electronics/IRC; Power_W: 63mW; TempCo: 10 ppm/C; Value_Code: 10k0; U/M: EA; Value: 10.0k; EIA_Code: E192; Res_ohm: 10k; SizeX_mm: 1; SizeY_mm: 0.5; SizeZ_mm: 0.6; Value2: 0.063W; AEC Qualified: N; VDC_V: 25V; AEC Category: Q200
TP9 TP10 TP17 = CMP-0055138-2: as TP12-TP16 on sheet INDSYS2971B_BiasPower
U8 = CMP-0065059-3: 3.3-V to 5-V RS-485 Transceivers with Auto-direction Control / and ±12-kV IEC ESD Protection; Manufacturer: Texas Instruments; Alternate PartNumber: THVD1426DR; SizeX_mm: 4.9; SizeY_mm: 6.2; CompType: IC; SizeZ_mm: 1.75; SizeArea_mm2: 30.38; SizeAreaWB_mm2: 56.58; AEC Category: Q200; AEC Qualified: N
U9 = CMP-0013250-3: TMP235DCK, DCK0005A (SOT-5); Manufacturer: Texas Instruments; SizeX_mm: 2.1; SizeY_mm: 2.0; CompType: IC; SizeZ_mm: 1.1; SizeArea_mm2: 4.2; SizeAreaWB_mm2: 9.3; AEC Category: Q200; AEC Qualified: N

## Sheet INDSYS2971B_Hardware.SchDoc
size 431 x 279 mm; Date: Not shown in title block; ApprovedBy: Not shown in title block; CheckedBy: Not shown in title block; Author: Not shown in title block; CompanyName: Not shown in title block; DrawnBy: Battery test; Engineer: Not shown in title block; Organization: Not shown in title block; Address1: Not shown in title block; Address2: Not shown in title block; Address3: Not shown in title block; Address4: Not shown in title block; DocumentNumber: 11; Revision: Use project parameter SCH_Rev; SheetNumber: 11; SheetTotal: 11; PageSetup: Record=PageOptions¦CenterHorizontal=True¦CenterVertical=True¦PrintScale=1.00¦XCorrection=1.00¦YCorrection=1.00¦PrintKind=0¦BorderSize=5000000¦LeftOffset=0¦BottomOffset=0¦Orientation=2¦PaperLength=1000¦PaperWidth=1000¦Scale=100¦PaperSource=15¦PrintQuality=600¦MediaType=1¦DitherType=10¦PaperKind=Letter¦PrintScaleMode=1
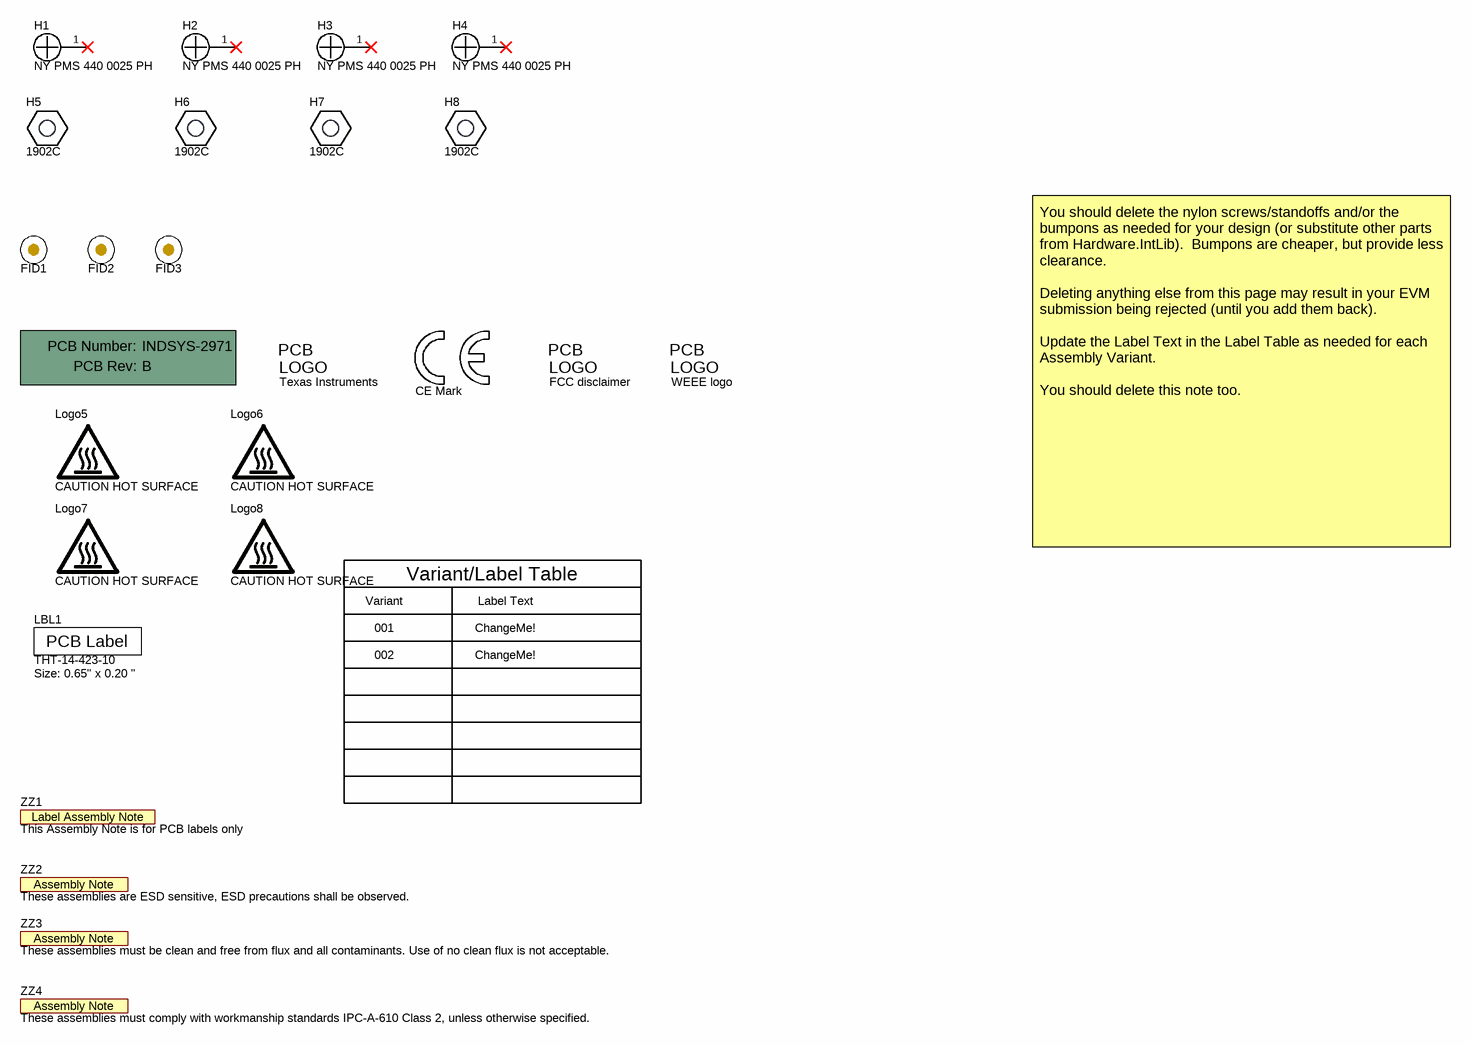
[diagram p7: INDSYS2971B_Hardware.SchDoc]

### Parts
!PCB1  Printed Circuit Board  (value not drawn)  (mechanical)
FID1  Fiducial  [Fiducial10-20]  (value not drawn)
FID2  Fiducial  [Fiducial10-20]  (value not drawn)
FID3  Fiducial  [Fiducial10-20]  (value not drawn)
H1  NY PMS 440 0025 PH  [NY PMS 440 0025 PH]
H2  NY PMS 440 0025 PH  [NY PMS 440 0025 PH]
H3  NY PMS 440 0025 PH  [NY PMS 440 0025 PH]
H4  NY PMS 440 0025 PH  [NY PMS 440 0025 PH]
H5  1902C  [Keystone_1902C]
H6  1902C  [Keystone_1902C]
H7  1902C  [Keystone_1902C]
H8  1902C  [Keystone_1902C]
LBL1  THT-14-423-10  Note: Size: 0.65" x 0.20 "  [Label_650x200]
Logo1  CE Mark  [CE_Mark_5mm]  (no BOM)
Logo2  Texas Instruments  [TI_Stacked_Overlay_Small]  (no BOM)
Logo3  FCC disclaimer  [FCC_disclaimer]  (no BOM)
Logo4  WEEE logo  [WEEE_Minimum]  (no BOM)
Logo5  CAUTION HOT SURFACE  [IEC_HotSurface_Large]  (no BOM)
Logo6  CAUTION HOT SURFACE  [IEC_HotSurface_Large]  (no BOM)
Logo7  CAUTION HOT SURFACE  [IEC_HotSurface_Large]  (no BOM)
Logo8  CAUTION HOT SURFACE  [IEC_HotSurface_Large]  (no BOM)
ZZ1  This Assembly Note is for PCB labels only  [AssemblyNoteLabel]  (no BOM)
ZZ2  These assemblies are ESD sensitive, ESD precautions shall be observed.  [AssemblyNote]  (no BOM)
ZZ3  These assemblies must be clean and free from flux and all contaminants. Use of no clean flux is not acceptable.  [AssemblyNote]  (no BOM)
ZZ4  These assemblies must comply with workmanship standards IPC-A-610 Class 2, unless otherwise specified.  [AssemblyNote]  (no BOM)

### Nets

Not connected (* = marked no-connect by the designer): H1 1*; H2 1*; H3 1*; H4 1*

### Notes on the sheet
- Variant
- Variant/Label Table
- Label Text
- You should delete the nylon screws/standoffs and/or the bumpons as needed for your design (or substitute other parts from Hardware.IntLib).  Bumpons are cheaper, but provide less clearance.
  Deleting anything else from this page may result in your EVM submission being rejected (until you add them back).
  Update the Label Text in the Label Table as needed for each Assembly Variant.
  You should delete this note too.
- 001
- 002
- ChangeMe!

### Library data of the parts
!PCB1 = CMP-0003618-2: Manufacturer: Any
FID1-FID3 = CMP-0077181-1: Fiducial mark.  There is nothing to buy or mount.
H1-H4 = CMP-0003617-1: Machine Screw, Round, #4-40 x 1/4, Nylon, Philips panhead; Manufacturer: B&F Fastener Supply; CompType: Hardware
H5-H8 = CMP-0003610-1: Standoff, Hex, 0.5"L #4-40 Nylon; Manufacturer: Keystone; CompType: Hardware
LBL1 = CMP-0003625-1: Thermal Transfer Printable Labels, 0.650" W x 0.200" H - 10,000 per roll; Manufacturer: Brady; CompType: Label
Logo1 = CMP-0074844-1: SymbolCreator: a0412235
Logo2 = CMP-0074838-1: Texas Instrument Corporate Signature; SymbolCreator: a0412235; Lib Reference: TI_Logo; Library Reference: Logo
Logo3 = CMP-0074847-1: FCC_disclaimer; Library Reference: Logo
Logo4 = CMP-0074769-3: Manufacturer: Texas Instruments; CompType: IC; AEC Category: Q200
Logo5-Logo8 = CMP-0074837-2: IEC 61010-1 Hot Surface Warning; Manufacturer: Texas Instruments; CompType: IC; AEC Category: Q200; SymbolCreator: a0412235
ZZ1 = CMP-0003616-3
ZZ2 = CMP-0077236-1
ZZ3 = CMP-0077237-1
ZZ4 = CMP-0077238-1

## Sheet INDSYS2971B_Cover.SchDoc
size 431 x 279 mm; Date: Not shown in title block; ApprovedBy: Not shown in title block; CheckedBy: Not shown in title block; Author: Not shown in title block; CompanyName: Not shown in title block; Engineer: Not shown in title block; Organization: Not shown in title block; Address1: Not shown in title block; Address2: Not shown in title block; Address3: Not shown in title block; Address4: Not shown in title block; DocumentNumber: 1; Revision: Use project parameter SCH_Rev; SheetNumber: 1; SheetTotal: 11; PageSetup: Record=PageOptions¦CenterHorizontal=True¦CenterVertical=True¦PrintScale=1.00¦XCorrection=1.00¦YCorrection=1.00¦PrintKind=0¦BorderSize=5000000¦LeftOffset=0¦BottomOffset=0¦Orientation=2¦PaperLength=1000¦PaperWidth=1000¦Scale=100¦PaperSource=15¦PrintQuality=600¦MediaType=1¦DitherType=10¦PaperKind=Letter¦PrintScaleMode=1
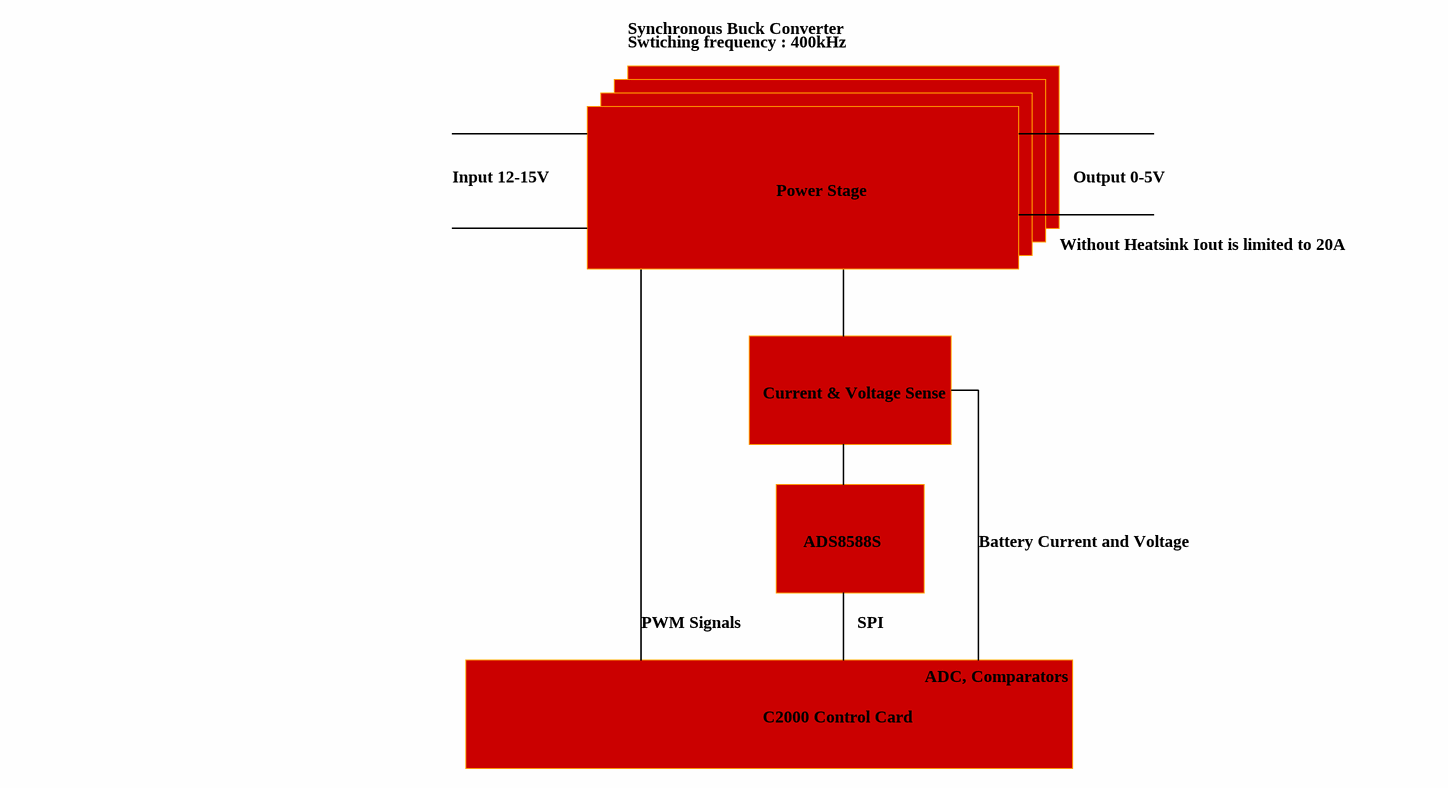
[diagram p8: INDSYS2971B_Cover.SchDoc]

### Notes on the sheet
- Synchronous Buck Converter
- Swtiching frequency : 400kHz
- Input 12-15V
- Power Stage
- Output 0-5V
- Without Heatsink Iout is limited to 20A
- Current & Voltage Sense
- ADS8588S
- Battery Current and Voltage
- PWM Signals
- SPI
- C2000 Control Card
- ADC, Comparators

## Sheet INDSYS2971B_CurrentSense.SchDoc
size 431 x 279 mm; Date: Not shown in title block; ApprovedBy: Not shown in title block; CheckedBy: Not shown in title block; Author: Not shown in title block; CompanyName: Not shown in title block; DrawnBy: Battery test; Engineer: Not shown in title block; Organization: Not shown in title block; Address1: Not shown in title block; Address2: Not shown in title block; Address3: Not shown in title block; Address4: Not shown in title block; DocumentNumber: 5; Revision: Use project parameter SCH_Rev; SheetNumber: 5; SheetTotal: 11; PageSetup: Record=PageOptions¦CenterHorizontal=True¦CenterVertical=True¦PrintScale=1.00¦XCorrection=1.00¦YCorrection=1.00¦PrintKind=0¦BorderSize=5000000¦LeftOffset=0¦BottomOffset=0¦Orientation=2¦PaperLength=1000¦PaperWidth=1000¦Scale=100¦PaperSource=15¦PrintQuality=600¦MediaType=1¦DitherType=10¦PaperKind=Letter¦PrintScaleMode=1
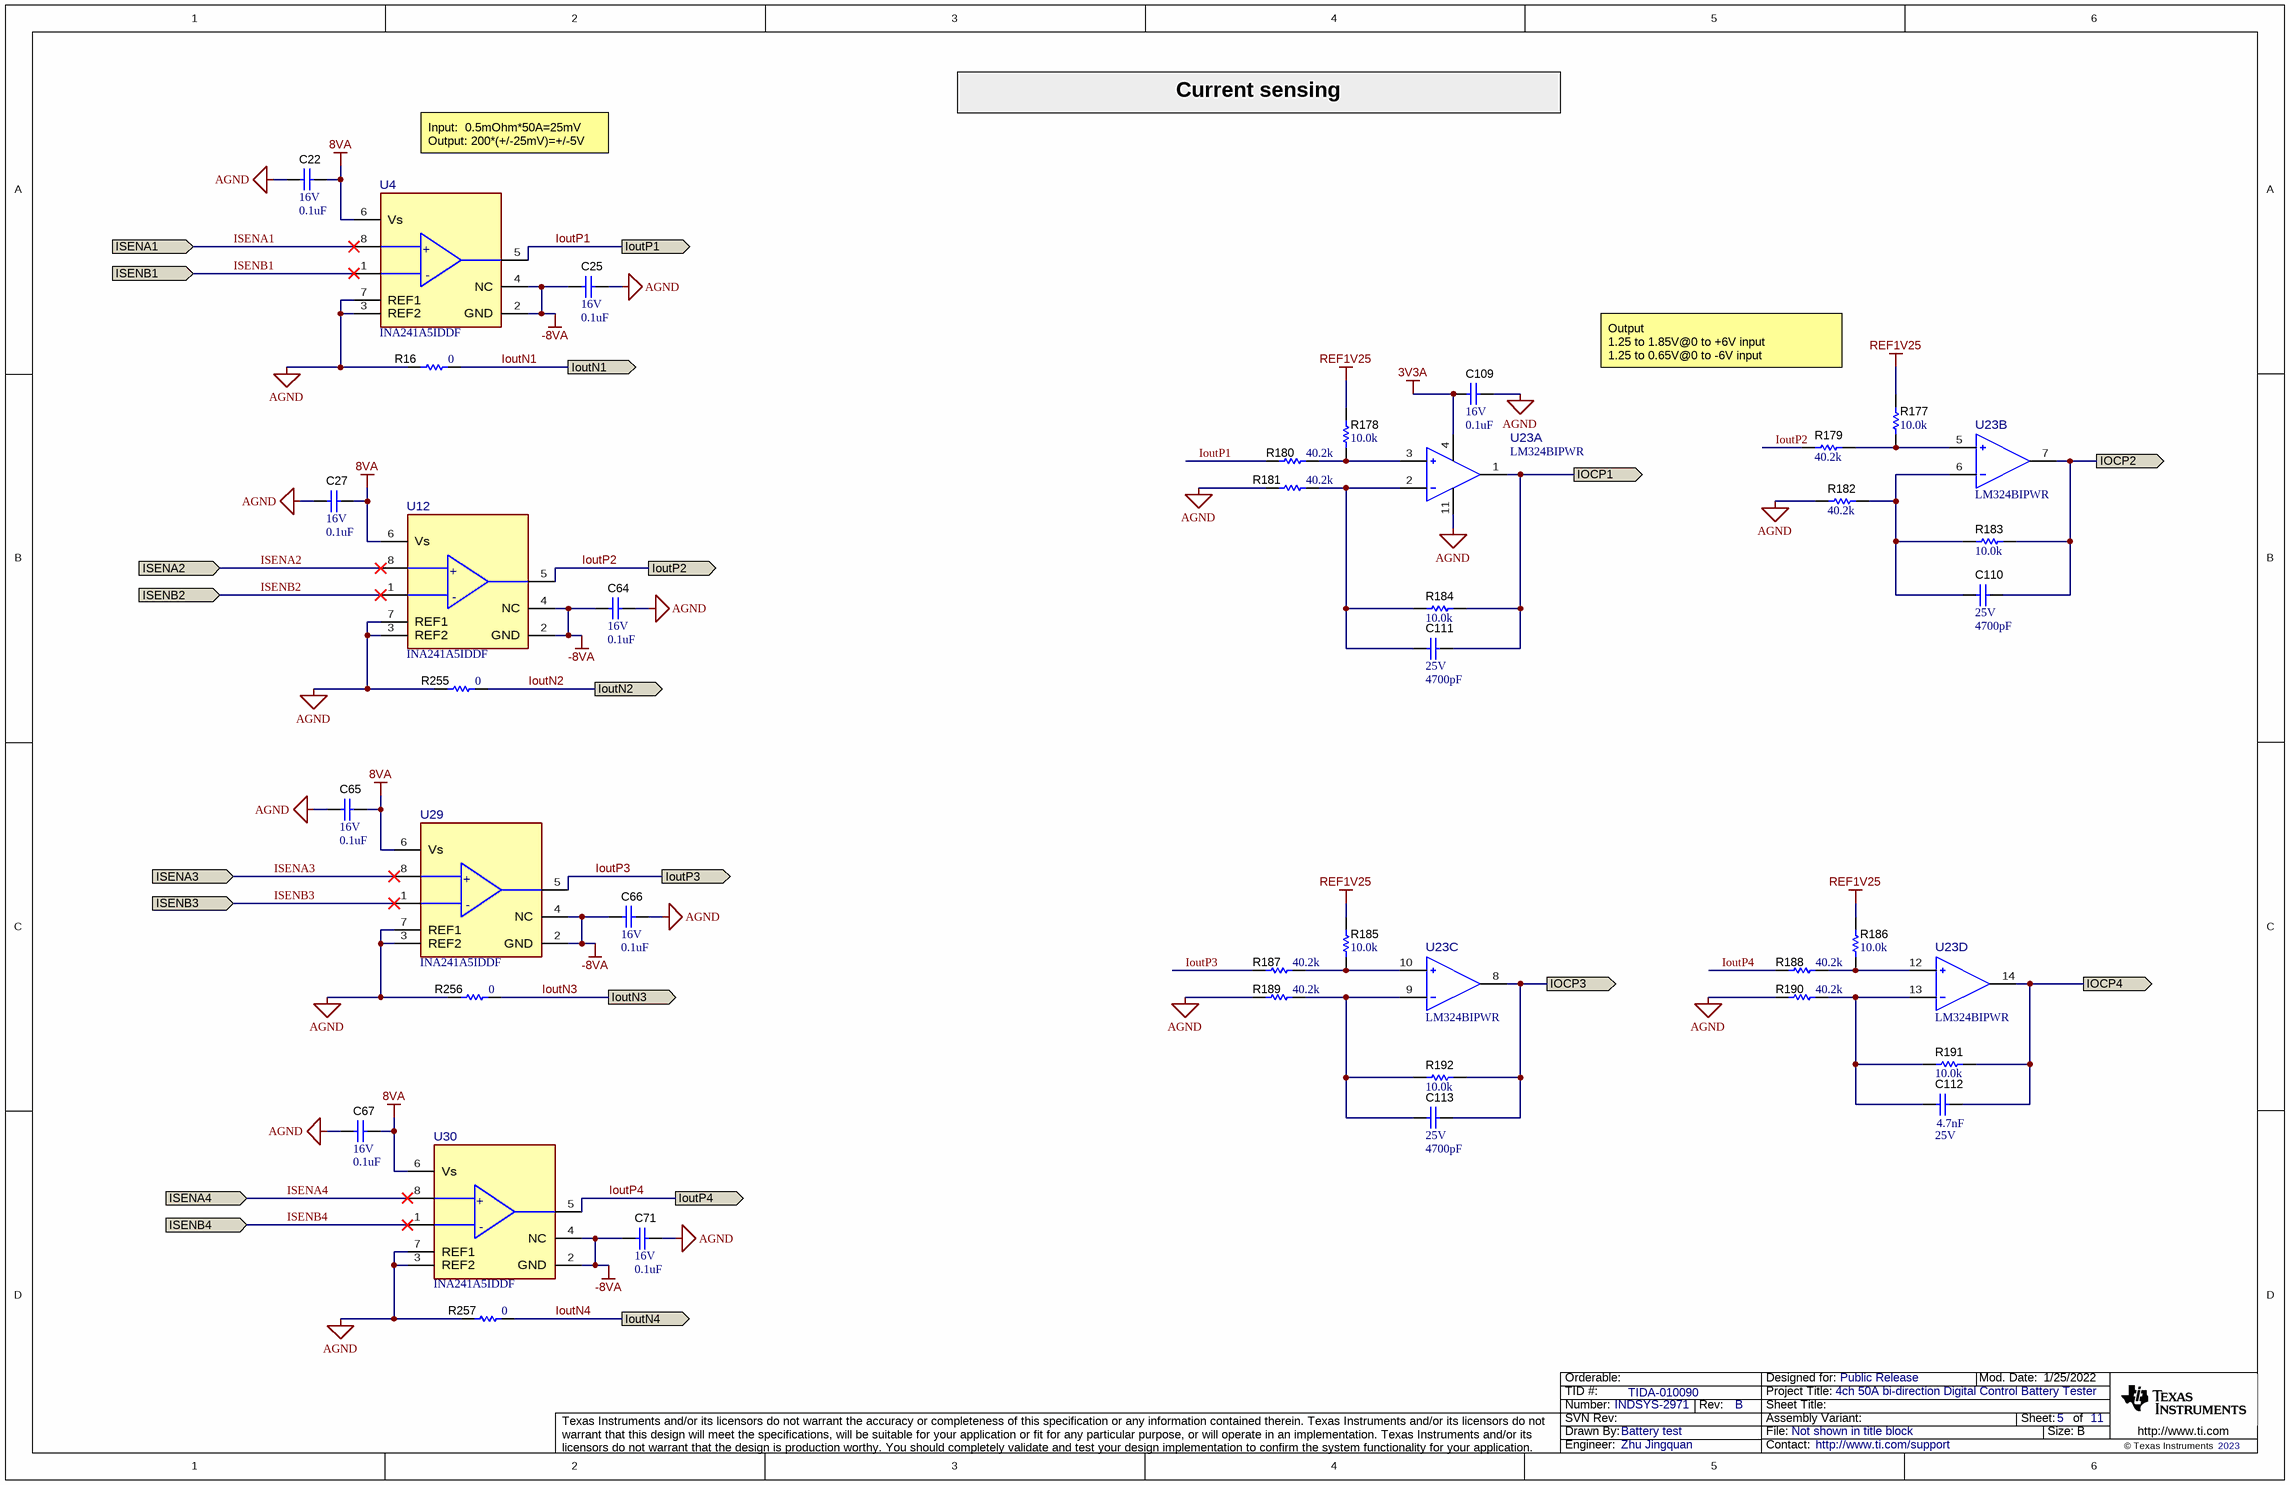
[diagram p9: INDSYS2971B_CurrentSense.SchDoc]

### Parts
C22  VDC_V: 16V  ValueDisplayed: 0.1uF  [0402]  (hidden comment: GRM155R61C104KA88D)
C25  VDC_V: 16V  ValueDisplayed: 0.1uF  [0402]  (hidden comment: GRM155R61C104KA88D)
C27  VDC_V: 16V  ValueDisplayed: 0.1uF  [0402]  (hidden comment: GRM155R61C104KA88D)
C64  VDC_V: 16V  ValueDisplayed: 0.1uF  [0402]  (hidden comment: GRM155R61C104KA88D)
C65  VDC_V: 16V  ValueDisplayed: 0.1uF  [0402]  (hidden comment: GRM155R61C104KA88D)
C66  VDC_V: 16V  ValueDisplayed: 0.1uF  [0402]  (hidden comment: GRM155R61C104KA88D)
C67  VDC_V: 16V  ValueDisplayed: 0.1uF  [0402]  (hidden comment: GRM155R61C104KA88D)
C71  VDC_V: 16V  ValueDisplayed: 0.1uF  [0402]  (hidden comment: GRM155R61C104KA88D)
C109  VDC_V: 16V  ValueDisplayed: 0.1uF  [0402]  (hidden comment: GRM155R61C104KA88D)
C110  VDC_V: 25V  ValueDisplayed: 4700pF  [0402]  (hidden comment: GRM155R61E472KA01D)
C111  VDC_V: 25V  ValueDisplayed: 4700pF  [0402]  (hidden comment: GRM155R61E472KA01D)
C112  Cap_F: 4.7nF  VDC_V: 25V  [0402]  (hidden comment: GRM155R61E472KA01D)
C113  VDC_V: 25V  ValueDisplayed: 4700pF  [0402]  (hidden comment: GRM155R61E472KA01D)
R16  ValueDisplayed: 0  [0402]  (hidden comment: CRCW04020000Z0ED)
R177  ValueDisplayed: 10.0k  [0402]  (hidden comment: PCF0402-12-10K0BT1)
R178  ValueDisplayed: 10.0k  [0402]  (hidden comment: PCF0402-12-10K0BT1)
R179  ValueDisplayed: 40.2k  [0402]  (hidden comment: CRCW040240K2FKED)
R180  ValueDisplayed: 40.2k  [0402]  (hidden comment: CRCW040240K2FKED)
R181  ValueDisplayed: 40.2k  [0402]  (hidden comment: CRCW040240K2FKED)
R182  ValueDisplayed: 40.2k  [0402]  (hidden comment: CRCW040240K2FKED)
R183  ValueDisplayed: 10.0k  [0402]  (hidden comment: PCF0402-12-10K0BT1)
R184  ValueDisplayed: 10.0k  [0402]  (hidden comment: PCF0402-12-10K0BT1)
R185  ValueDisplayed: 10.0k  [0402]  (hidden comment: PCF0402-12-10K0BT1)
R186  ValueDisplayed: 10.0k  [0402]  (hidden comment: PCF0402-12-10K0BT1)
R187  ValueDisplayed: 40.2k  [0402]  (hidden comment: CRCW040240K2FKED)
R188  ValueDisplayed: 40.2k  [0402]  (hidden comment: CRCW040240K2FKED)
R189  ValueDisplayed: 40.2k  [0402]  (hidden comment: CRCW040240K2FKED)
R190  ValueDisplayed: 40.2k  [0402]  (hidden comment: CRCW040240K2FKED)
R191  ValueDisplayed: 10.0k  [0402]  (hidden comment: PCF0402-12-10K0BT1)
R192  ValueDisplayed: 10.0k  [0402]  (hidden comment: PCF0402-12-10K0BT1)
R255  ValueDisplayed: 0  [0402]  (hidden comment: CRCW04020000Z0ED)
R256  ValueDisplayed: 0  [0402]  (hidden comment: CRCW04020000Z0ED)
R257  ValueDisplayed: 0  [0402]  (hidden comment: CRCW04020000Z0ED)
U4  INA241A5IDDF  [DDF0008A-MFG]
U12  INA241A5IDDF  [DDF0008A-MFG]
U23  LM324BIPWR  [PW0014A-MFG]  (parts A,B,C,D of 4)
U29  INA241A5IDDF  [DDF0008A-MFG]
U30  INA241A5IDDF  [DDF0008A-MFG]

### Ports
IOCP1 (out), IOCP2 (out), IOCP3 (out), IOCP4 (out), IoutN1 (out), IoutN2 (out), IoutN3 (out), IoutN4 (out), IoutP1 (out), IoutP2 (out), IoutP3 (out), IoutP4 (out), ISENA1 (in), ISENA2 (in), ISENA3 (in), ISENA4 (in), ISENB1 (in), ISENB2 (in), ISENB3 (in), ISENB4 (in)

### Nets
3V3A: C109.2 U23.4(VCC+)
8VA: C22.1 C27.1 C65.1 C67.1 U4.6(Vs) U12.6(Vs) U29.6(Vs) U30.6(Vs)
-8VA: C25.2 C64.2 C66.2 C71.2 U4.2(GND) U4.4(NC) U12.2(GND) U12.4(NC) U29.2(GND) U29.4(NC) U30.2(GND) U30.4(NC)
AGND: C22.2 C25.1 C27.2 C64.1 C65.2 C66.1 C67.2 C71.1 C109.1 R16.1 R181.1 R182.1 R189.1 R190.1 R255.1 R256.1 R257.1 U4.3(REF2) U4.7(REF1) U12.3(REF2) U12.7(REF1) U23.11(VCC-) U29.3(REF2) U29.7(REF1) U30.3(REF2) U30.7(REF1)
REF1V25: R177.2 R178.2 R185.2 R186.2
IOCP1: C111.1 R184.1 U23.1(1OUT) ; port IOCP1
IOCP2: C110.1 R183.1 U23.7(2OUT) ; port IOCP2
IOCP3: C113.1 R192.1 U23.8(3OUT) ; port IOCP3
IOCP4: C112.1 R191.1 U23.14(4OUT) ; port IOCP4
IoutN1: R16.2 ; port IoutN1
IoutN2: R255.2 ; port IoutN2
IoutN3: R256.2 ; port IoutN3
IoutN4: R257.2 ; port IoutN4
IoutP1: R180.1 U4.5(OUT) ; port IoutP1
IoutP2: R179.1 U12.5(OUT) ; port IoutP2
IoutP3: R187.1 U29.5(OUT) ; port IoutP3
IoutP4: R188.1 U30.5(OUT) ; port IoutP4
ISENA1: U4.8(IN+) ; port ISENA1
ISENA2: U12.8(IN+) ; port ISENA2
ISENA3: U29.8(IN+) ; port ISENA3
ISENA4: U30.8(IN+) ; port ISENA4
ISENB1: U4.1(IN-) ; port ISENB1
ISENB2: U12.1(IN-) ; port ISENB2
ISENB3: U29.1(IN-) ; port ISENB3
ISENB4: U30.1(IN-) ; port ISENB4
NetC110_2: C110.2 R182.2 R183.2 U23.6(2IN-)
NetC111_2: C111.2 R181.2 R184.2 U23.2(1IN-)
NetC112_2: C112.2 R190.2 R191.2 U23.13(4IN-)
NetC113_2: C113.2 R189.2 R192.2 U23.9(3IN-)
NetR177_1: R177.1 R179.2 U23.5(2IN+)
NetR178_1: R178.1 R180.2 U23.3(1IN+)
NetR185_1: R185.1 R187.2 U23.10(3IN+)
NetR186_1: R186.1 R188.2 U23.12(4IN+)

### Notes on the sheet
- Input:  0.5mOhm*50A=25mV
  Output: 200*(+/-25mV)=+/-5V
- Current sensing
- Output
  1.25 to 1.85V@0 to +6V input
  1.25 to 0.65V@0 to -6V input

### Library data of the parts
C22 C25 C27 C64-C67 C71 C109 = CMP-0006591-2: as C83 on sheet INDSYS2971B_BiasPower
C110 C111 C113 = CMP-0006611-2: CAP, CERM, 4700 pF, 25 V, +/- 10%, X5R, 0402; Manufacturer: MuRata; TaMin_C: -55°C; Polarized: N; SizeAreaWB_mm2: 3; Value1: Unknown; U/M: EA; Value: 4700pF; TaMax_C: 85°C; SizeZ_mm: 0.6; SizeX_mm: 1; SizeY_mm: 0.5; Cap_F: 4.7nF; AEC Category: Q200
C112 = CMP-0006611-2: CAP, CERM, 4700 pF, 25 V, +/- 10%, X5R, 0402; Manufacturer: MuRata; TaMin_C: -55°C; Polarized: N; SizeAreaWB_mm2: 3; Value1: Unknown; U/M: EA; Value: 4700pF; TaMax_C: 85°C; SizeZ_mm: 0.6; SizeX_mm: 1; SizeY_mm: 0.5; AEC Category: Q200
R16 R255-R257 = CMP-0026822-3: as R36-R46 on sheet INDSYS2971B_ControlCard
R177 R178 R183-R186 R191 R192 = CMP-0026796-1: as R127 on sheet INDSYS2971B_BiasPower
R179-R182 R187-R190 = CMP-0026367-2: as R118 on sheet INDSYS2971B_BiasPower
U4 U12 U29 U30 = CMP-0093651-2: -4-V to 110-V, Bidirectional, Ultra-Precise Current Sense Amplifier With Enhanced PWM Rejection; Manufacturer: Texas Instruments; Bandwidth: 1MHz; TaMax_C: +125°C; Max Supply Voltage: 20V; Nominal Supply Current: 2.5mA; Number Of Channels: 1; Min Supply Voltage: 2.7V; Input Bias Current: 40uA; Response Time: 1.5us; AEC Category: Q200; TaMin_C: -40°C; Input Offset Voltage: 0.002mV; CompType: IC; AEC Qualified: No; TJmax_C: +150°C; SizeZ_mm: 1.1mm; Standoff Height: 0mm; Voltage Gain: 0.2V/mV
U23 = CMP-0120501-1: Quad, 36-V, 1.2-MHz 3-mV offset voltage operational amplifier; Manufacturer: Texas Instruments; SizeZ_mm: 1.2mm; AEC Qualified: No; Gain Bandwidth: 1.2MHz; Input Bias Current: -0.01uA; Input Offset Voltage: 0.6mV; Max Dual Supply Voltage: 18V; Max Supply Voltage: 36V; Min Dual Supply Voltage: 2.5V; Min Supply Voltage: 5V; Nominal Supply Current: 240-350uA; Number Of Channels: 4; Output Current Per Channel: 20mA; Response Time: 4us; Standoff Height: 0.05mm; TaMax_C: +85°C; TaMin_C: -40°C; TJmax_C: +150°C; Voltage Gain: 100V/mV

## Sheet INDSYS2971B_VoltageSense.SchDoc
size 431 x 279 mm; Date: Not shown in title block; ApprovedBy: Not shown in title block; CheckedBy: Not shown in title block; Author: Not shown in title block; CompanyName: Not shown in title block; DrawnBy: Battery test; Engineer: Not shown in title block; Organization: Not shown in title block; Address1: Not shown in title block; Address2: Not shown in title block; Address3: Not shown in title block; Address4: Not shown in title block; DocumentNumber: 6; Revision: Use project parameter SCH_Rev; SheetNumber: 6; SheetTotal: 11; PageSetup: Record=PageOptions¦CenterHorizontal=True¦CenterVertical=True¦PrintScale=1.00¦XCorrection=1.00¦YCorrection=1.00¦PrintKind=0¦BorderSize=5000000¦LeftOffset=0¦BottomOffset=0¦Orientation=2¦PaperLength=1000¦PaperWidth=1000¦Scale=100¦PaperSource=15¦PrintQuality=600¦MediaType=1¦DitherType=10¦PaperKind=Letter¦PrintScaleMode=1
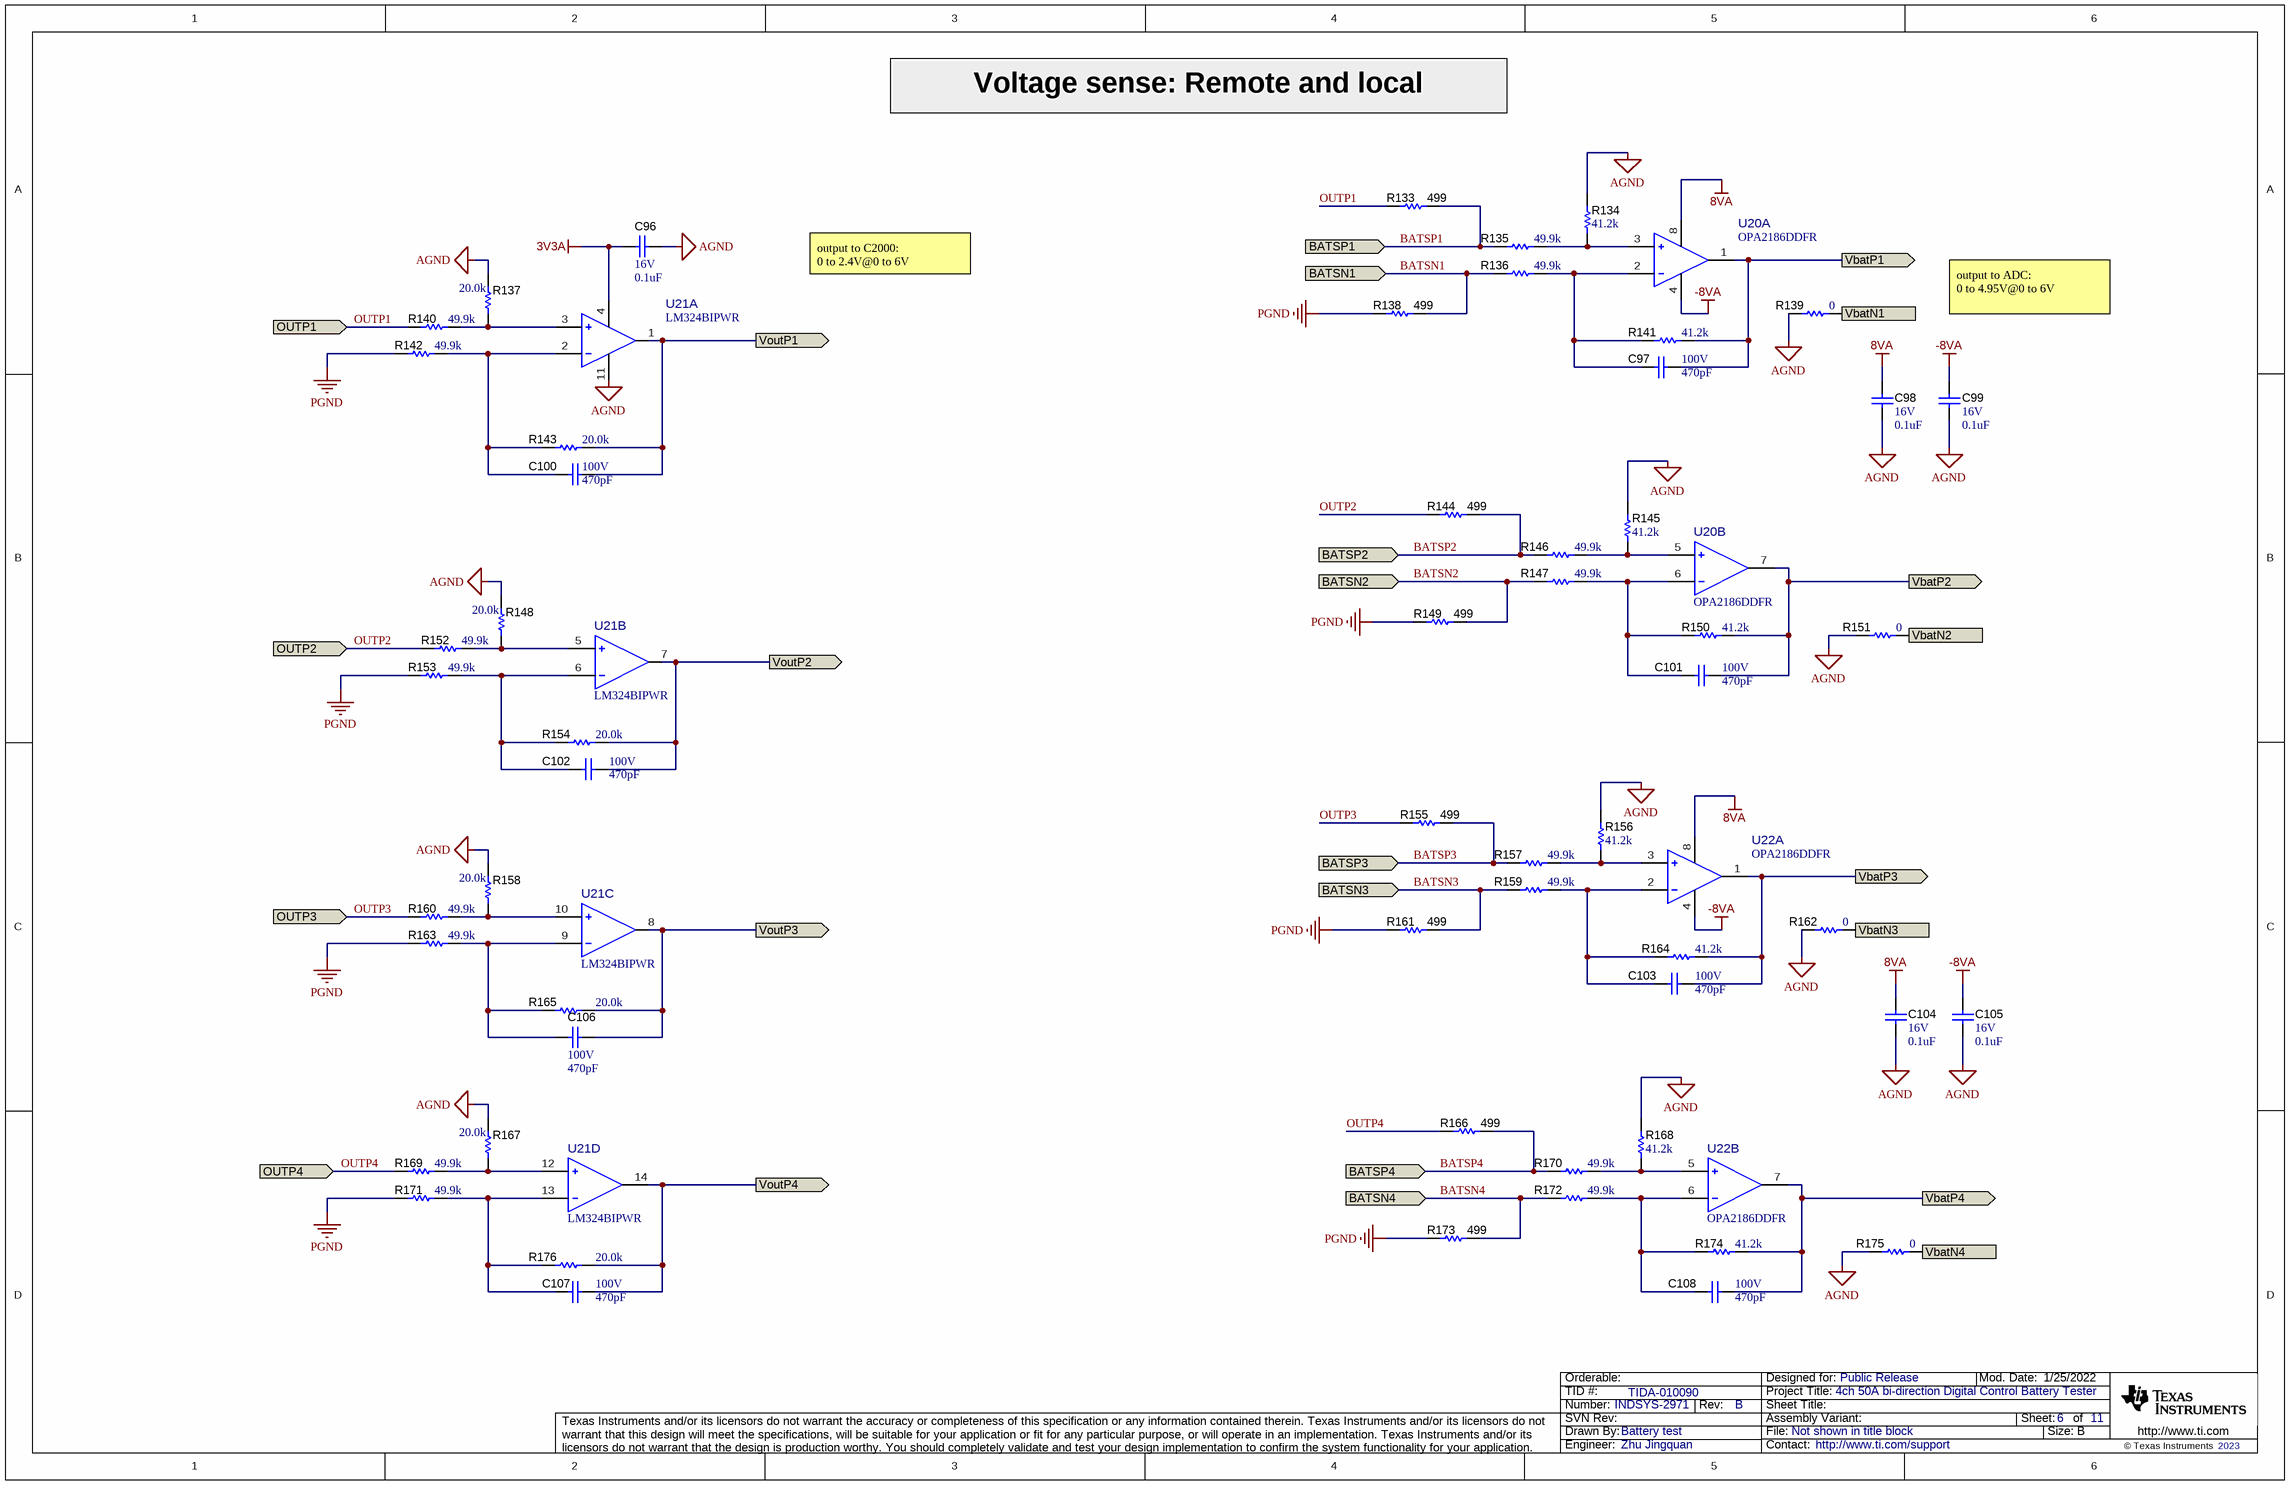
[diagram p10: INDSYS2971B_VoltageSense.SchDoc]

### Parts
C96  VDC_V: 16V  ValueDisplayed: 0.1uF  [0402]  (hidden comment: GRM155R61C104KA88D)
C97  VDC_V: 100V  ValueDisplayed: 470pF  [0402]  (hidden comment: GRM155R72A471KA01D)
C98  VDC_V: 16V  ValueDisplayed: 0.1uF  [0402]  (hidden comment: GRM155R61C104KA88D)
C99  VDC_V: 16V  ValueDisplayed: 0.1uF  [0402]  (hidden comment: GRM155R61C104KA88D)
C100  VDC_V: 100V  ValueDisplayed: 470pF  [0402]  (hidden comment: GRM155R72A471KA01D)
C101  VDC_V: 100V  ValueDisplayed: 470pF  [0402]  (hidden comment: GRM155R72A471KA01D)
C102  VDC_V: 100V  ValueDisplayed: 470pF  [0402]  (hidden comment: GRM155R72A471KA01D)
C103  VDC_V: 100V  ValueDisplayed: 470pF  [0402]  (hidden comment: GRM155R72A471KA01D)
C104  VDC_V: 16V  ValueDisplayed: 0.1uF  [0402]  (hidden comment: GRM155R61C104KA88D)
C105  VDC_V: 16V  ValueDisplayed: 0.1uF  [0402]  (hidden comment: GRM155R61C104KA88D)
C106  VDC_V: 100V  ValueDisplayed: 470pF  [0402]  (hidden comment: GRM155R72A471KA01D)
C107  VDC_V: 100V  ValueDisplayed: 470pF  [0402]  (hidden comment: GRM155R72A471KA01D)
C108  VDC_V: 100V  ValueDisplayed: 470pF  [0402]  (hidden comment: GRM155R72A471KA01D)
R133  ValueDisplayed: 499  [0402]  (hidden comment: CRCW0402499RFKED)
R134  ValueDisplayed: 41.2k  [0402]  (hidden comment: CRCW040241K2FKED)
R135  ValueDisplayed: 49.9k  [0402]  (hidden comment: CRCW040249K9FKED)
R136  ValueDisplayed: 49.9k  [0402]  (hidden comment: CRCW040249K9FKED)
R137  ValueDisplayed: 20.0k  [0402]  (hidden comment: CRCW040220K0FKED)
R138  ValueDisplayed: 499  [0402]  (hidden comment: CRCW0402499RFKED)
R139  ValueDisplayed: 0  [0402]  (hidden comment: CRCW04020000Z0ED)
R140  ValueDisplayed: 49.9k  [0402]  (hidden comment: CRCW040249K9FKED)
R141  ValueDisplayed: 41.2k  [0402]  (hidden comment: CRCW040241K2FKED)
R142  ValueDisplayed: 49.9k  [0402]  (hidden comment: CRCW040249K9FKED)
R143  ValueDisplayed: 20.0k  [0402]  (hidden comment: CRCW040220K0FKED)
R144  ValueDisplayed: 499  [0402]  (hidden comment: CRCW0402499RFKED)
R145  ValueDisplayed: 41.2k  [0402]  (hidden comment: CRCW040241K2FKED)
R146  ValueDisplayed: 49.9k  [0402]  (hidden comment: CRCW040249K9FKED)
R147  ValueDisplayed: 49.9k  [0402]  (hidden comment: CRCW040249K9FKED)
R148  ValueDisplayed: 20.0k  [0402]  (hidden comment: CRCW040220K0FKED)
R149  ValueDisplayed: 499  [0402]  (hidden comment: CRCW0402499RFKED)
R150  ValueDisplayed: 41.2k  [0402]  (hidden comment: CRCW040241K2FKED)
R151  ValueDisplayed: 0  [0402]  (hidden comment: CRCW04020000Z0ED)
R152  ValueDisplayed: 49.9k  [0402]  (hidden comment: CRCW040249K9FKED)
R153  ValueDisplayed: 49.9k  [0402]  (hidden comment: CRCW040249K9FKED)
R154  ValueDisplayed: 20.0k  [0402]  (hidden comment: CRCW040220K0FKED)
R155  ValueDisplayed: 499  [0402]  (hidden comment: CRCW0402499RFKED)
R156  ValueDisplayed: 41.2k  [0402]  (hidden comment: CRCW040241K2FKED)
R157  ValueDisplayed: 49.9k  [0402]  (hidden comment: CRCW040249K9FKED)
R158  ValueDisplayed: 20.0k  [0402]  (hidden comment: CRCW040220K0FKED)
R159  ValueDisplayed: 49.9k  [0402]  (hidden comment: CRCW040249K9FKED)
R160  ValueDisplayed: 49.9k  [0402]  (hidden comment: CRCW040249K9FKED)
R161  ValueDisplayed: 499  [0402]  (hidden comment: CRCW0402499RFKED)
R162  ValueDisplayed: 0  [0402]  (hidden comment: CRCW04020000Z0ED)
R163  ValueDisplayed: 49.9k  [0402]  (hidden comment: CRCW040249K9FKED)
R164  ValueDisplayed: 41.2k  [0402]  (hidden comment: CRCW040241K2FKED)
R165  ValueDisplayed: 20.0k  [0402]  (hidden comment: CRCW040220K0FKED)
R166  ValueDisplayed: 499  [0402]  (hidden comment: CRCW0402499RFKED)
R167  ValueDisplayed: 20.0k  [0402]  (hidden comment: CRCW040220K0FKED)
R168  ValueDisplayed: 41.2k  [0402]  (hidden comment: CRCW040241K2FKED)
R169  ValueDisplayed: 49.9k  [0402]  (hidden comment: CRCW040249K9FKED)
R170  ValueDisplayed: 49.9k  [0402]  (hidden comment: CRCW040249K9FKED)
R171  ValueDisplayed: 49.9k  [0402]  (hidden comment: CRCW040249K9FKED)
R172  ValueDisplayed: 49.9k  [0402]  (hidden comment: CRCW040249K9FKED)
R173  ValueDisplayed: 499  [0402]  (hidden comment: CRCW0402499RFKED)
R174  ValueDisplayed: 41.2k  [0402]  (hidden comment: CRCW040241K2FKED)
R175  ValueDisplayed: 0  [0402]  (hidden comment: CRCW04020000Z0ED)
R176  ValueDisplayed: 20.0k  [0402]  (hidden comment: CRCW040220K0FKED)
U20  OPA2186DDFR  [DDF0008A-MFG]  (parts A,B of 2)
U21  LM324BIPWR  [PW0014A-MFG]  (parts A,B,C,D of 4)
U22  OPA2186DDFR  [DDF0008A-MFG]  (parts A,B of 2)

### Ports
BATSN1 (in), BATSN2 (in), BATSN3 (in), BATSN4 (in), BATSP1 (in), BATSP2 (in), BATSP3 (in), BATSP4 (in), OUTP1 (in), OUTP2 (in), OUTP3 (in), OUTP4 (in), VbatN1 (out), VbatN2 (out), VbatN3 (out), VbatN4 (out), VbatP1 (out), VbatP2 (out), VbatP3 (out), VbatP4 (out), VoutP1 (out), VoutP2 (out), VoutP3 (out), VoutP4 (out)

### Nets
3V3A: C96.2 U21.4(VCC+)
8VA: C98.2 C104.2 U20.8(V+) U22.8(V+)
-8VA: C99.2 C105.2 U20.4(V-) U22.4(V-)
AGND: C96.1 C98.1 C99.1 C104.1 C105.1 R134.2 R137.2 R139.1 R145.2 R148.2 R151.1 R156.2 R158.2 R162.1 R167.2 R168.2 R175.1 U21.11(VCC-)
PGND: R138.1 R142.1 R149.1 R153.1 R161.1 R163.1 R171.1 R173.1
BATSN1: R136.1 R138.2 ; port BATSN1
BATSN2: R147.1 R149.2 ; port BATSN2
BATSN3: R159.1 R161.2 ; port BATSN3
BATSN4: R172.1 R173.2 ; port BATSN4
BATSP1: R133.2 R135.1 ; port BATSP1
BATSP2: R144.2 R146.1 ; port BATSP2
BATSP3: R155.2 R157.1 ; port BATSP3
BATSP4: R166.2 R170.1 ; port BATSP4
OUTP1: R133.1 R140.1 ; port OUTP1
OUTP2: R144.1 R152.1 ; port OUTP2
OUTP3: R155.1 R160.1 ; port OUTP3
OUTP4: R166.1 R169.1 ; port OUTP4
VbatN1: R139.2 ; port VbatN1
VbatN2: R151.2 ; port VbatN2
VbatN3: R162.2 ; port VbatN3
VbatN4: R175.2 ; port VbatN4
VbatP1: C97.2 R141.1 U20.1(OUT_A) ; port VbatP1
VbatP2: C101.2 R150.1 U20.7(OUT_B) ; port VbatP2
VbatP3: C103.2 R164.1 U22.1(OUT_A) ; port VbatP3
VbatP4: C108.2 R174.1 U22.7(OUT_B) ; port VbatP4
VoutP1: C100.2 R143.2 U21.1(1OUT) ; port VoutP1
VoutP2: C102.2 R154.2 U21.7(2OUT) ; port VoutP2
VoutP3: C106.2 R165.2 U21.8(3OUT) ; port VoutP3
VoutP4: C107.2 R176.2 U21.14(4OUT) ; port VoutP4
NetC97_1: C97.1 R136.2 R141.2 U20.2(-IN_A)
NetC100_1: C100.1 R142.2 R143.1 U21.2(1IN-)
NetC101_1: C101.1 R147.2 R150.2 U20.6(-IN_B)
NetC102_1: C102.1 R153.2 R154.1 U21.6(2IN-)
NetC103_1: C103.1 R159.2 R164.2 U22.2(-IN_A)
NetC106_1: C106.1 R163.2 R165.1 U21.9(3IN-)
NetC107_1: C107.1 R171.2 R176.1 U21.13(4IN-)
NetC108_1: C108.1 R172.2 R174.2 U22.6(-IN_B)
NetR134_1: R134.1 R135.2 U20.3(+IN_A)
NetR137_1: R137.1 R140.2 U21.3(1IN+)
NetR145_1: R145.1 R146.2 U20.5(+IN_B)
NetR148_1: R148.1 R152.2 U21.5(2IN+)
NetR156_1: R156.1 R157.2 U22.3(+IN_A)
NetR158_1: R158.1 R160.2 U21.10(3IN+)
NetR167_1: R167.1 R169.2 U21.12(4IN+)
NetR168_1: R168.1 R170.2 U22.5(+IN_B)

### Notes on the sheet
- Voltage sense: Remote and local
- output to C2000:
  0 to 2.4V@0 to 6V
- output to ADC:
  0 to 4.95V@0 to 6V

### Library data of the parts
C96 C98 C99 C104 C105 = CMP-0006591-2: as C83 on sheet INDSYS2971B_BiasPower
C97 C100-C103 C106-C108 = CMP-0006711-2: CAP, CERM, 470 pF, 100 V, +/- 10%, X7R, 0402; Manufacturer: MuRata; TaMin_C: -55°C; Polarized: N; SizeAreaWB_mm2: 3; Value1: Unknown; U/M: EA; Value: 470pF; TaMax_C: 125°C; SizeZ_mm: 0.6; SizeX_mm: 1; SizeY_mm: 0.5; AEC Category: Q200
R133 R138 R144 R149 R155 R161 R166 R173 = CMP-0026402-2: RES, 499, 1%, 0.063 W, AEC-Q200 Grade 0, 0402; Manufacturer: Vishay-Dale; Power_W: 63mW; TempCo: 100 ppm/C; Value_Code: 499R; Value: 499; EIA_Code: E96; SizeX_mm: 1; SizeY_mm: 0.5; SizeZ_mm: 0.6; Value2: 0.063W; AEC Qualified: Y; VDC_V: 50V; AEC Category: Q200; AEC Grade: 0
R134 R141 R145 R150 R156 R164 R168 R174 = CMP-0026371-2: RES, 41.2 k, 1%, 0.063 W, AEC-Q200 Grade 0, 0402; Manufacturer: Vishay-Dale; Power_W: 63mW; TempCo: 100 ppm/C; Value_Code: 41k2; Value: 41.2k; EIA_Code: E96; SizeX_mm: 1; SizeY_mm: 0.5; SizeZ_mm: 0.6; Value2: 0.063W; AEC Qualified: Y; VDC_V: 50V; AEC Category: Q200; AEC Grade: 0
R135 R136 R140 R142 R146 R147 R152 R153 R157 R159 R160 R163 R169-R172 = CMP-0026403-2: RES, 49.9 k, 1%, 0.063 W, AEC-Q200 Grade 0, 0402; Manufacturer: Vishay-Dale; Power_W: 63mW; TempCo: 100 ppm/C; Value_Code: 49k9; Value: 49.9k; EIA_Code: E96; SizeX_mm: 1; SizeY_mm: 0.5; SizeZ_mm: 0.6; Value2: 0.063W; AEC Qualified: Y; VDC_V: 50V; AEC Category: Q200; AEC Grade: 0
R137 R143 R148 R154 R158 R165 R167 R176 = CMP-0026162-2: RES, 20.0 k, 1%, 0.063 W, AEC-Q200 Grade 0, 0402; Manufacturer: Vishay-Dale; Power_W: 63mW; TempCo: 100 ppm/C; Value: 20.0k; Res_ohm: 20k; SizeZ_mm: 0.6; AEC Qualified: Y; VDC_V: 50V; Value_Code: 20k0; EIA_Code: E96; SizeX_mm: 1; SizeY_mm: 0.5; Value2: 0.063W; AEC Category: Q200; AEC Grade: 0
R139 R151 R162 R175 = CMP-0026822-3: as R36-R46 on sheet INDSYS2971B_ControlCard
U20 U22 = CMP-0098326-1: Precision, Rail-to-Rail Input and Output, 24-V, Zero-Drift Operational Amplifiers; Manufacturer: Texas Instruments; SizeZ_mm: 1.1mm; AEC Qualified: No; Gain Bandwidth: 750kHz; Input Bias Current: 0.000005uA; Input Offset Voltage: 0.001mV; Max Dual Supply Voltage: 12V; Max Supply Voltage: 24V; Min Dual Supply Voltage: 2.25V; Min Supply Voltage: 4.5V; Nominal Supply Current: 90uA; Number Of Channels: 2; Output Current Per Channel: 20mA; Response Time: 7.5us; Standoff Height: 0mm; TaMax_C: +125°C; TaMin_C: -40°C; TJmax_C: +150°C; Voltage Gain: 148dB
U21 = CMP-0120501-1: as U23 on sheet INDSYS2971B_CurrentSense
